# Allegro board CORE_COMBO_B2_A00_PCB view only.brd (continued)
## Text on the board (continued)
User.45: list("[Package] BOTTOM" "275.Pkg to Place Keepout Spacing" "0 MIL [NONE]" "138.58 MIL" "-138.58 MIL" "DRC ERROR CLASS/PACKAGE_BOTTOM" "[Shape] Package Keepout/Bottom ((-3125.93 3041.94) (-2426.72 3992.42))" "[Shape] Package Geometry/Place_Bound_Bottom ((-3045.92 3121.96) (-2506.71 3912.44))" list(-3026.600000 3824.480000) nil)@@@list("kelly1_pan" "2016/03/17 14:53:36" nil "P143000035-PC" "10i-core_combo_b2.20")@@@list("jennifer_hsu" "2016/03/21 14:55:31" nil "p143000039-pc" "10i-core_combo_b2.20") | list("[Package] BOTTOM" "276.Pkg to Place Keepin Spacing" "0 MIL [NONE]" "0 MIL" "0.00 MIL" "DRC ERROR CLASS/PACKAGE_BOTTOM" "[Shape] Package Keepin/All ((-2957.43 -894.53) (7886.82 5054.84))" "[Shape] Package Geometry/Place_Bound_Bottom ((-3045.92 3121.96) (-2506.71 3912.44))" list(-2927.260000 3167.040000) nil)@@@list("kelly1_pan" "2016/03/17 14:53:36" nil "P143000035-PC" "10i-core_combo_b2.20")@@@list("jennifer_hsu" "2016/03/21 14:55:32" nil "p143000039-pc" "10i-core_combo_b2.20") | list("[Package] BOTTOM" "274.Pkg to Place Keepout Spacing" "0 MIL [NONE]" "138.58 MIL" "-138.58 MIL" "DRC ERROR CLASS/PACKAGE_BOTTOM" "[Shape] Package Keepout/Bottom ((-3125.93 2331.37) (-2370.0 3171.49))" "[Shape] Package Geometry/Place_Bound_Bottom ((-3045.92 3121.96) (-2506.71 3912.44))" list(-2927.260000 3125.380000) nil)@@@list("kelly1_pan" "2016/03/17 14:53:35" nil "P143000035-PC" "10i-core_combo_b2.20")@@@list("jennifer_hsu" "2016/03/21 14:55:30" nil "p143000039-pc" "10i-core_combo_b2.20") | list("[Package] BOTTOM" "213.Pkg to Place Keepin Spacing" "0 MIL [NONE]" "955.34 MIL" "-955.34 MIL" "DRC ERROR CLASS/PACKAGE_BOTTOM" "[Shape] Package Keepin/All ((-2957.43 -894.53) (7886.82 5054.84))" "[Shape] Package Geometry/Place_Bound_Bottom ((-3386.36 5554.88) (-3226.36 5714.88))" list(-2913.710000 4676.880000) nil)@@@list("kelly1_pan" "2016/03/17 14:53:52" nil "P143000035-PC" "10i-core_combo_b2.20")@@@list("jennifer_hsu" "2016/03/21 14:54:25" nil "p143000039-pc" "10i-core_combo_b2.20") | list("[Package] TOP" "154.Pkg to Place Keepin Spacing" "0 MIL [NONE]" "955.34 MIL" "-955.34 MIL" "DRC ERROR CLASS/PACKAGE_TOP" "[Shape] Package Keepin/All ((-2957.43 -894.53) (7886.82 5054.84))" "[Shape] Package Geometry/Place_Bound_Top ((-3386.36 5554.88) (-3226.36 5714.88))" list(-2913.710000 4676.880000) nil)@@@list("kelly1_pan" "2016/03/17 14:57:43" nil "P143000035-PC" "10i-core_combo_b2.20")@@@list("jennifer_hsu" "2016/03/21 14:52:20" nil "p143000039-pc" "10i-core_combo_b2.20") | list("[Package] BOTTOM" "216.Pkg to Place Keepin Spacing" "0 MIL [NONE]" "0 MIL" "0.00 MIL" "DRC ERROR CLASS/PACKAGE_BOTTOM" "[Shape] Package Keepin/All ((-2957.43 -894.53) (7886.82 5054.84))" "[Shape] Package Geometry/Place_Bound_Bottom ((-2929.39 4429.59) (-2642.39 4716.59))" list(-2831.290000 4436.960000) nil)@@@list("kelly1_pan" "2016/03/17 14:57:00" nil "P143000035-PC" "10i-core_combo_b2.20")@@@list("jennifer_hsu" "2016/03/21 14:54:28" nil "p143000039-pc" "10i-core_combo_b2.20") | list("[Package] TOP" "189.Pkg to Place Keepin Spacing" "0 MIL [NONE]" "0 MIL" "0.00 MIL" "DRC ERROR CLASS/PACKAGE_TOP" "[Shape] Package Keepin/All ((-2957.43 -894.53) (7886.82 5054.84))" "[Shape] Package Geometry/Place_Bound_Top ((-2929.39 4429.59) (-2642.39 4716.59))" list(-2831.290000 4436.960000) nil)@@@list("kelly1_pan" "2016/03/17 14:59:18" nil "P143000035-PC" "10i-core_combo_b2.20")@@@list("jennifer_hsu" "2016/03/21 14:54:01" nil "p143000039-pc" "10i-core_combo_b2.20") | list("[Package] BOTTOM" "259.Pkg to Place Keepout Spacing" "0 MIL [NONE]" "122.44 MIL" "-122.44 MIL" "DRC ERROR CLASS/PACKAGE_BOTTOM" "[Shape] Package Keepout/Bottom ((-3125.93 3041.94) (-2426.72 3992.42))" "[Shape] Package Geometry/Place_Bound_Bottom ((-3045.93 2411.38) (-2421.17 3091.5))" list(-2733.360000 3041.940000) nil)@@@list("kelly1_pan" "2016/03/17 14:57:22" nil "P143000035-PC" "10i-core_combo_b2.20")@@@list("jennifer_hsu" "2016/03/21 14:55:14" nil "p143000039-pc" "10i-core_combo_b2.20") | list("[Package] BOTTOM" "226.Pkg to Place Keepin Spacing" "0 MIL [NONE]" "44.66 MIL" "-44.66 MIL" "DRC ERROR CLASS/PACKAGE_BOTTOM" "[Shape] Package Keepin/All ((-2957.43 -894.53) (7886.82 5054.84))" "[Shape] Package Geometry/Place_Bound_Bottom ((-2705.5 3802.3) (-2665.5 3842.3))" list(-2688.180000 3886.900000) nil)@@@list("kelly1_pan" "2016/03/17 14:57:08" nil "P143000035-PC" "10i-core_combo_b2.20")@@@list("jennifer_hsu" "2016/03/21 14:54:38" nil "p143000039-pc" "10i-core_combo_b2.20") | list("[Package] TOP" "162.Pkg to Place Keepin Spacing" "0 MIL [NONE]" "44.66 MIL" "-44.66 MIL" "DRC ERROR CLASS/PACKAGE_TOP" "[Shape] Package Keepin/All ((-2957.43 -894.53) (7886.82 5054.84))" "[Shape] Package Geometry/Place_Bound_Top ((-2705.5 3802.3) (-2665.5 3842.3))" list(-2688.180000 3886.900000) nil)@@@list("kelly1_pan" "2016/03/17 14:57:28" nil "P143000035-PC" "10i-core_combo_b2.20")@@@list("jennifer_hsu" "2016/03/21 14:52:33" nil "p143000039-pc" "10i-core_combo_b2.20") | list("[Electrical] ALL" "120.Diffpair Max Uncoupled Length" "200 MIL [DIFFP_UNCOUPLED_LENGTH]" "294.69 MIL" "-94.69 MIL" "DRC ERROR CLASS/ALL" "[PinPair] <uTiL>cId3288<uTiL>.G53:<uTiL>cId4175<uTiL>.7 ((1239.78 2945.81) (-2647.3 3458.14))" "[PinPair] <uTiL>cId3288<uTiL>.F53:<uTiL>cId4175<uTiL>.9 ((1239.78 2971.41) (-2647.3 3497.51))" list(-2647.300000 3497.510000) nil)@@@list("kelly1_pan" "2016/03/17 14:52:43" nil "P143000035-PC" "10i-core_combo_b2.20")@@@list("jennifer_hsu" "2016/03/21 14:51:00" nil "p143000039-pc" "10i-core_combo_b2.20") | list("[Electrical] ALL" "116.Diffpair Max Uncoupled Length" "200 MIL [DIFFP_UNCOUPLED_LENGTH]" "316.78 MIL" "-116.78 MIL" "DRC ERROR CLASS/ALL" "[PinPair] <uTiL>cId3288<uTiL>.F55:<uTiL>cId4175<uTiL>.1 ((1203.78 2971.41) (-2647.3 3340.03))" "[PinPair] <uTiL>cId3288<uTiL>.E55:<uTiL>cId4175<uTiL>.3 ((1203.78 2997.01) (-2647.3 3379.4))" list(-2647.300000 3379.400000) nil)@@@list("kelly1_pan" "2016/03/17 14:52:38" nil "P143000035-PC" "10i-core_combo_b2.20")@@@list("jennifer_hsu" "2016/03/21 14:50:56" nil "p143000039-pc" "10i-core_combo_b2.20") | list("[Package] BOTTOM" "227.Pkg to Place Keepin Spacing" "0 MIL [NONE]" "44.68 MIL" "-44.68 MIL" "DRC ERROR CLASS/PACKAGE_BOTTOM" "[Shape] Package Keepin/All ((-2957.43 -894.53) (7886.82 5054.84))" "[Shape] Package Geometry/Place_Bound_Bottom ((-2705.5 3192.06) (-2665.5 3232.06))" list(-2625.080000 3235.140000) nil)@@@list("kelly1_pan" "2016/03/17 14:53:51" nil "P143000035-PC" "10i-core_combo_b2.20")@@@list("jennifer_hsu" "2016/03/21 14:54:39" nil "p143000039-pc" "10i-core_combo_b2.20") | list("[Package] TOP" "163.Pkg to Place Keepin Spacing" "0 MIL [NONE]" "44.68 MIL" "-44.68 MIL" "DRC ERROR CLASS/PACKAGE_TOP" "[Shape] Package Keepin/All ((-2957.43 -894.53) (7886.82 5054.84))" "[Shape] Package Geometry/Place_Bound_Top ((-2705.5 3192.06) (-2665.5 3232.06))" list(-2625.080000 3235.140000) nil)@@@list("kelly1_pan" "2016/03/17 14:59:17" nil "P143000035-PC" "10i-core_combo_b2.20")@@@list("jennifer_hsu" "2016/03/21 14:53:36" nil "p143000039-pc" "10i-core_combo_b2.20") | list("[Electrical] ALL" "122.Diffpair Max Uncoupled Length" "200 MIL [DIFFP_UNCOUPLED_LENGTH]" "290.05 MIL" "-90.05 MIL" "DRC ERROR CLASS/ALL" "[PinPair] <uTiL>cId3288<uTiL>.G56:<uTiL>cId4175<uTiL>.10 ((1167.78 2945.81) (-2586.28 3517.2))" "[PinPair] <uTiL>cId3288<uTiL>.F56:<uTiL>cId4175<uTiL>.12 ((1167.78 2971.41) (-2586.28 3556.57))" list(-2586.280000 3556.570000) nil)@@@list("kelly1_pan" "2016/03/17 14:52:45" nil "P143000035-PC" "10i-core_combo_b2.20")@@@list("jennifer_hsu" "2016/03/21 14:51:02" nil "p143000039-pc" "10i-core_combo_b2.20") | list("[Electrical] ALL" "118.Diffpair Max Uncoupled Length" "200 MIL [DIFFP_UNCOUPLED_LENGTH]" "290.3 MIL" "-90.30 MIL" "DRC ERROR CLASS/ALL" "[PinPair] <uTiL>cId3288<uTiL>.F58:<uTiL>cId4175<uTiL>.4 ((1131.78 2971.41) (-2586.28 3399.09))" "[PinPair] <uTiL>cId3288<uTiL>.E58:<uTiL>cId4175<uTiL>.6 ((1131.78 2997.01) (-2586.28 3438.46))" list(-2586.280000 3438.460000) nil)@@@list("kelly1_pan" "2016/03/17 14:52:41" nil "P143000035-PC" "10i-core_combo_b2.20")@@@list("jennifer_hsu" "2016/03/21 14:50:58" nil "p143000039-pc" "10i-core_combo_b2.20") | list("[Package] BOTTOM" "225.Pkg to Place Keepin Spacing" "0 MIL [NONE]" "44.66 MIL" "-44.66 MIL" "DRC ERROR CLASS/PACKAGE_BOTTOM" "[Shape] Package Keepin/All ((-2957.43 -894.53) (7886.82 5054.84))" "[Shape] Package Geometry/Place_Bound_Bottom ((-2583.45 2997.18) (-2543.45 3037.18))" list(-2549.080000 3080.230000) nil)@@@list("kelly1_pan" "2016/03/17 14:53:50" nil "P143000035-PC" "10i-core_combo_b2.20")@@@list("jennifer_hsu" "2016/03/21 14:54:37" nil "p143000039-pc" "10i-core_combo_b2.20") | list("[Package] TOP" "186.Pkg to Place Keepin Spacing" "0 MIL [NONE]" "44.66 MIL" "-44.66 MIL" "DRC ERROR CLASS/PACKAGE_TOP" "[Shape] Package Keepin/All ((-2957.43 -894.53) (7886.82 5054.84))" "[Shape] Package Geometry/Place_Bound_Top ((-2583.45 2997.18) (-2543.45 3037.18))" list(-2549.080000 3080.230000) nil)@@@list("kelly1_pan" "2016/03/17 14:57:42" nil "P143000035-PC" "10i-core_combo_b2.20")@@@list("jennifer_hsu" "2016/03/21 14:53:58" nil "p143000039-pc" "10i-core_combo_b2.20") | list("[Electrical] ALL" "129.Diffpair Max Uncoupled Length" "200 MIL [DIFFP_UNCOUPLED_LENGTH]" "310.32 MIL" "-110.32 MIL" "DRC ERROR CLASS/ALL" "[PinPair] <uTiL>cId4161<uTiL>.8:<uTiL>cId3288<uTiL>.C15 ((-2514.24 2830.18) (2090.69 3053.01))" "[PinPair] <uTiL>cId4161<uTiL>.9:<uTiL>cId3288<uTiL>.D15 ((-2514.24 2908.92) (2090.69 3027.41))" list(-2514.240000 2908.920000) nil)@@@list("kelly1_pan" "2016/03/17 14:52:53" nil "P143000035-PC" "10i-core_combo_b2.20")@@@list("jennifer_hsu" "2016/03/21 14:51:13" nil "p143000039-pc" "10i-core_combo_b2.20") | list("[Electrical] ALL" "127.Diffpair Max Uncoupled Length" "200 MIL [DIFFP_UNCOUPLED_LENGTH]" "285.42 MIL" "-85.42 MIL" "DRC ERROR CLASS/ALL" "[PinPair] <uTiL>cId4161<uTiL>.5:<uTiL>cId3288<uTiL>.E10 ((-2514.24 2593.96) (2211.78 2997.01))" "[PinPair] <uTiL>cId4161<uTiL>.6:<uTiL>cId3288<uTiL>.F10 ((-2514.24 2672.7) (2211.78 2971.41))" list(-2514.240000 2672.700000) nil)@@@list("kelly1_pan" "2016/03/17 14:52:51" nil "P143000035-PC" "10i-core_combo_b2.20")@@@list("jennifer_hsu" "2016/03/21 14:51:10" nil "p143000039-pc" "10i-core_combo_b2.20") | list("[Package] BOTTOM" "260.Pkg to Place Keepin Spacing" "0 MIL [NONE]" "0 MIL" "0.00 MIL" "DRC ERROR CLASS/PACKAGE_BOTTOM" "[Shape] Package Keepin/All ((-2957.43 -894.53) (7886.82 5054.84))" "[Shape] Package Geometry/Place_Bound_Bottom ((-3045.93 2411.38) (-2421.17 3091.5))" list(-2502.520000 2463.960000) nil)@@@list("kelly1_pan" "2016/03/17 14:57:22" nil "P143000035-PC" "10i-core_combo_b2.20")@@@list("jennifer_hsu" "2016/03/21 14:55:15" nil "p143000039-pc" "10i-core_combo_b2.20") | list("[Package] BOTTOM" "238.Pkg to Place Keepin Spacing" "0 MIL [NONE]" "44.68 MIL" "-44.68 MIL" "DRC ERROR CLASS/PACKAGE_BOTTOM" "[Shape] Package Keepin/All ((-2957.43 -894.53) (7886.82 5054.84))" "[Shape] Package Geometry/Place_Bound_Bottom ((-2583.45 2465.68) (-2543.45 2505.68))" list(-2498.770000 2485.680000) nil)@@@list("kelly1_pan" "2016/03/17 14:53:41" nil "P143000035-PC" "10i-core_combo_b2.20")@@@list("jennifer_hsu" "2016/03/21 14:54:49" nil "p143000039-pc" "10i-core_combo_b2.20") | list("[Package] TOP" "159.Pkg to Place Keepin Spacing" "0 MIL [NONE]" "44.68 MIL" "-44.68 MIL" "DRC ERROR CLASS/PACKAGE_TOP" "[Shape] Package Keepin/All ((-2957.43 -894.53) (7886.82 5054.84))" "[Shape] Package Geometry/Place_Bound_Top ((-2583.45 2465.68) (-2543.45 2505.68))" list(-2498.770000 2485.680000) nil)@@@list("kelly1_pan" "2016/03/17 14:57:27" nil "P143000035-PC" "10i-core_combo_b2.20")@@@list("jennifer_hsu" "2016/03/21 14:52:29" nil "p143000039-pc" "10i-core_combo_b2.20") | list("[Package] BOTTOM" "248.Pkg to Place Keepin Spacing" "0 MIL [NONE]" "44.67 MIL" "-44.67 MIL" "DRC ERROR CLASS/PACKAGE_BOTTOM" "[Shape] Package Keepin/All ((-2957.43 -894.53) (7886.82 5054.84))" "[Shape] Package Geometry/Place_Bound_Bottom ((-2487.78 4371.98) (-2447.78 4411.98))" list(-2441.380000 4451.010000) nil)@@@list("kelly1_pan" "2016/03/17 14:57:19" nil "P143000035-PC" "10i-core_combo_b2.20")@@@list("jennifer_hsu" "2016/03/21 14:54:59" nil "p143000039-pc" "10i-core_combo_b2.20") | list("[Package] TOP" "195.Pkg to Place Keepin Spacing" "0 MIL [NONE]" "44.67 MIL" "-44.67 MIL" "DRC ERROR CLASS/PACKAGE_TOP" "[Shape] Package Keepin/All ((-2957.43 -894.53) (7886.82 5054.84))" "[Shape] Package Geometry/Place_Bound_Top ((-2487.78 4371.98) (-2447.78 4411.98))" list(-2441.380000 4451.010000) nil)@@@list("kelly1_pan" "2016/03/17 14:59:17" nil "P143000035-PC" "10i-core_combo_b2.20")@@@list("jennifer_hsu" "2016/03/21 14:54:07" nil "p143000039-pc" "10i-core_combo_b2.20") | list("[Package] BOTTOM" "249.Pkg to Place Keepin Spacing" "0 MIL [NONE]" "44.67 MIL" "-44.67 MIL" "DRC ERROR CLASS/PACKAGE_BOTTOM" "[Shape] Package Keepin/All ((-2957.43 -894.53) (7886.82 5054.84))" "[Shape] Package Geometry/Place_Bound_Bottom ((-2487.78 3958.6) (-2447.78 3998.6))" list(-2422.780000 4025.040000) nil)@@@list("kelly1_pan" "2016/03/17 14:53:41" nil "P143000035-PC" "10i-core_combo_b2.20")@@@list("jennifer_hsu" "2016/03/21 14:55:00" nil "p143000039-pc" "10i-core_combo_b2.20") | list("[Package] TOP" "185.Pkg to Place Keepin Spacing" "0 MIL [NONE]" "44.67 MIL" "-44.67 MIL" "DRC ERROR CLASS/PACKAGE_TOP" "[Shape] Package Keepin/All ((-2957.43 -894.53) (7886.82 5054.84))" "[Shape] Package Geometry/Place_Bound_Top ((-2487.78 3958.6) (-2447.78 3998.6))" list(-2422.780000 4025.040000) nil)@@@list("kelly1_pan" "2016/03/17 14:57:47" nil "P143000035-PC" "10i-core_combo_b2.20")@@@list("jennifer_hsu" "2016/03/21 14:53:57" nil "p143000039-pc" "10i-core_combo_b2.20") | list("[Package] BOTTOM" "258.Pkg to Place Keepout Spacing" "0 MIL [NONE]" "122.44 MIL" "-122.44 MIL" "DRC ERROR CLASS/PACKAGE_BOTTOM" "[Shape] Package Keepout/Bottom ((-3125.93 2331.37) (-2370.0 3171.49))" "[Shape] Package Geometry/Place_Bound_Bottom ((-3045.93 2411.38) (-2421.17 3091.5))" list(-2421.170000 2712.070000) nil)@@@list("kelly1_pan" "2016/03/17 14:57:21" nil "P143000035-PC" "10i-core_combo_b2.20")@@@list("jennifer_hsu" "2016/03/21 14:55:11" nil "p143000039-pc" "10i-core_combo_b2.20") | list("[Package] TOP" "156.Pkg to Pkg Spacing" "0 MIL [PACKAGE_HEIGHT_MIN]" "27.56 MIL" "-27.56 MIL" "DRC ERROR CLASS/PACKAGE_TOP" "[Shape] Package Geometry/Place_Bound_Top ((-2379.19 3654.37) (-2252.81 3725.63))" "[Shape] Package Geometry/Place_Bound_Top ((-2377.02 3646.69) (-2254.98 3733.31))" list(-2377.020000 3654.370000) nil)@@@list("kelly1_pan" "2016/03/17 14:59:12" nil "P143000035-PC" "10i-core_combo_b2.20")@@@list("jennifer_hsu" "2016/03/21 14:52:22" nil "p143000039-pc" "10i-core_combo_b2.20") | list("[Package] TOP" "164.Pkg to Pkg Spacing" "0 MIL [PACKAGE_HEIGHT_MIN]" "27.56 MIL" "-27.56 MIL" "DRC ERROR CLASS/PACKAGE_TOP" "[Shape] Package Geometry/Place_Bound_Top ((-2379.19 3554.37) (-2252.81 3625.63))" "[Shape] Package Geometry/Place_Bound_Top ((-2377.02 3546.69) (-2254.98 3633.31))" list(-2377.020000 3554.370000) nil)@@@list("kelly1_pan" "2016/03/17 14:57:45" nil "P143000035-PC" "10i-core_combo_b2.20")@@@list("jennifer_hsu" "2016/03/21 14:53:37" nil "p143000039-pc" "10i-core_combo_b2.20") | list("[Package] TOP" "179.Pkg to Pkg Spacing" "0 MIL [PACKAGE_HEIGHT_MIN]" "27.56 MIL" "-27.56 MIL" "DRC ERROR CLASS/PACKAGE_TOP" "[Shape] Package Geometry/Place_Bound_Top ((-2379.19 3455.37) (-2252.81 3526.63))" "[Shape] Package Geometry/Place_Bound_Top ((-2377.02 3447.69) (-2254.98 3534.31))" list(-2377.020000 3455.370000) nil)@@@list("kelly1_pan" "2016/03/17 15:01:00" nil "P143000035-PC" "10i-core_combo_b2.20")@@@list("jennifer_hsu" "2016/03/21 14:53:51" nil "p143000039-pc" "10i-core_combo_b2.20") | list("[Package] TOP" "191.Pkg to Pkg Spacing" "0 MIL [PACKAGE_HEIGHT_MIN]" "27.56 MIL" "-27.56 MIL" "DRC ERROR CLASS/PACKAGE_TOP" "[Shape] Package Geometry/Place_Bound_Top ((-2379.19 3354.37) (-2252.81 3425.63))" "[Shape] Package Geometry/Place_Bound_Top ((-2377.02 3346.69) (-2254.98 3433.31))" list(-2377.020000 3354.370000) nil)@@@list("kelly1_pan" "2016/03/17 14:59:19" nil "P143000035-PC" "10i-core_combo_b2.20")@@@list("jennifer_hsu" "2016/03/21 14:54:03" nil "p143000039-pc" "10i-core_combo_b2.20") | list("[Package] BOTTOM" "254.Pkg to Place Keepin Spacing" "0 MIL [NONE]" "0 MIL" "0.00 MIL" "DRC ERROR CLASS/PACKAGE_BOTTOM" "[Shape] Package Keepin/All ((-2957.43 -894.53) (7886.82 5054.84))" "[Shape] Package Geometry/Place_Bound_Bottom ((-2338.84 2393.37) (-2051.84 2680.37))" list(-2304.780000 2444.050000) nil)@@@list("kelly1_pan" "2016/03/17 14:53:40" nil "P143000035-PC" "10i-core_combo_b2.20")@@@list("jennifer_hsu" "2016/03/21 14:55:07" nil "p143000039-pc" "10i-core_combo_b2.20") | list("[Package] TOP" "193.Pkg to Place Keepin Spacing" "0 MIL [NONE]" "0 MIL" "0.00 MIL" "DRC ERROR CLASS/PACKAGE_TOP" "[Shape] Package Keepin/All ((-2957.43 -894.53) (7886.82 5054.84))" "[Shape] Package Geometry/Place_Bound_Top ((-2338.84 2393.37) (-2051.84 2680.37))" list(-2304.780000 2444.050000) nil)@@@list("kelly1_pan" "2016/03/17 15:00:52" nil "P143000035-PC" "10i-core_combo_b2.20")@@@list("jennifer_hsu" "2016/03/21 14:54:05" nil "p143000039-pc" "10i-core_combo_b2.20") | list("[Package] BOTTOM" "234.Pkg to Pkg Spacing" "0 MIL [PACKAGE_HEIGHT_MIN]" "27.56 MIL" "-27.56 MIL" "DRC ERROR CLASS/PACKAGE_BOTTOM" "[Shape] Package Geometry/Place_Bound_Bottom ((-2303.69 2808.37) (-2177.31 2879.63))" "[Shape] Package Geometry/Place_Bound_Bottom ((-2301.52 2800.69) (-2179.48 2887.31))" list(-2301.520000 2808.370000) nil)@@@list("kelly1_pan" "2016/03/17 14:57:03" nil "P143000035-PC" "10i-core_combo_b2.20")@@@list("jennifer_hsu" "2016/03/21 14:54:46" nil "p143000039-pc" "10i-core_combo_b2.20") | list("[Package] TOP" "177.Pkg to Place Keepin Spacing" "0 MIL [NONE]" "862.94 MIL" "-862.94 MIL" "DRC ERROR CLASS/PACKAGE_TOP" "[Shape] Package Keepin/All ((-2957.43 -894.53) (7886.82 5054.84))" "[Shape] Package Geometry/Place_Bound_Top ((-2351.42 5539.82) (-2161.3 5729.94))" list(-2256.350000 4676.880000) nil)@@@list("kelly1_pan" "2016/03/17 15:00:56" nil "P143000035-PC" "10i-core_combo_b2.20")@@@list("jennifer_hsu" "2016/03/21 14:53:49" nil "p143000039-pc" "10i-core_combo_b2.20") | list("[Package] BOTTOM" "219.Pkg to Pkg Spacing" "0 MIL [PACKAGE_HEIGHT_MIN]" "27.56 MIL" "-27.56 MIL" "DRC ERROR CLASS/PACKAGE_BOTTOM" "[Shape] Package Geometry/Place_Bound_Bottom ((-2223.31 4307.57) (-2096.93 4378.83))" "[Shape] Package Geometry/Place_Bound_Bottom ((-2221.14 4299.89) (-2099.1 4386.51))" list(-2221.140000 4307.570000) nil)@@@list("kelly1_pan" "2016/03/17 14:53:26" nil "P143000035-PC" "10i-core_combo_b2.20")@@@list("jennifer_hsu" "2016/03/21 14:54:31" nil "p143000039-pc" "10i-core_combo_b2.20") | list("[Package] TOP" "165.Pkg to Pkg Spacing" "0 MIL [PACKAGE_HEIGHT_MIN]" "27.56 MIL" "-27.56 MIL" "DRC ERROR CLASS/PACKAGE_TOP" "[Shape] Package Geometry/Place_Bound_Top ((-2208.19 2814.37) (-2081.81 2885.63))" "[Shape] Package Geometry/Place_Bound_Top ((-2206.02 2806.69) (-2083.98 2893.31))" list(-2206.020000 2814.370000) nil)@@@list("kelly1_pan" "2016/03/17 14:57:31" nil "P143000035-PC" "10i-core_combo_b2.20")@@@list("jennifer_hsu" "2016/03/21 14:53:38" nil "p143000039-pc" "10i-core_combo_b2.20") | list("[Package] TOP" "173.Pkg to Pkg Spacing" "0 MIL [PACKAGE_HEIGHT_MIN]" "27.56 MIL" "-27.56 MIL" "DRC ERROR CLASS/PACKAGE_TOP" "[Shape] Package Geometry/Place_Bound_Top ((-2208.19 2724.37) (-2081.81 2795.63))" "[Shape] Package Geometry/Place_Bound_Top ((-2206.02 2716.69) (-2083.98 2803.31))" list(-2206.020000 2724.370000) nil)@@@list("kelly1_pan" "2016/03/17 14:57:38" nil "P143000035-PC" "10i-core_combo_b2.20")@@@list("jennifer_hsu" "2016/03/21 14:53:45" nil "p143000039-pc" "10i-core_combo_b2.20") | list("[Package] BOTTOM" "271.Pkg to Place Keepin Spacing" "0 MIL [NONE]" "862.94 MIL" "-862.94 MIL" "DRC ERROR CLASS/PACKAGE_BOTTOM" "[Shape] Package Keepin/All ((-2957.43 -894.53) (7886.82 5054.84))" "[Shape] Package Geometry/Place_Bound_Bottom ((-2151.42 5539.82) (-1961.3 5729.94))" list(-2056.370000 4676.880000) nil)@@@list("kelly1_pan" "2016/03/17 14:53:33" nil "P143000035-PC" "10i-core_combo_b2.20")@@@list("jennifer_hsu" "2016/03/21 14:55:27" nil "p143000039-pc" "10i-core_combo_b2.20") | list("[Package] BOTTOM" "246.Pkg to Pkg Spacing" "0 MIL [PACKAGE_HEIGHT_MIN]" "342.52 MIL" "-342.52 MIL" "DRC ERROR CLASS/PACKAGE_BOTTOM" "[Shape] Package Geometry/Place_Bound_Bottom ((-2637.27 4460.93) (-2030.57 4662.05))" "[Shape] Package Geometry/Place_Bound_Bottom ((-2055.44 3647.63) (-1701.85 4533.61))" list(-2055.440000 4511.100000) nil)@@@list("kelly1_pan" "2016/03/17 14:57:03" nil "P143000035-PC" "10i-core_combo_b2.20")@@@list("jennifer_hsu" "2016/03/21 14:54:57" nil "p143000039-pc" "10i-core_combo_b2.20") | list("[Electrical] ALL" "106.Diffpair Max Uncoupled Length" "200 MIL [DIFFP_UNCOUPLED_LENGTH]" "205.57 MIL" "-5.57 MIL" "DRC ERROR CLASS/ALL" "[PinPair] <uTiL>cId6551<uTiL>.5:<uTiL>cId3288<uTiL>.AF8 ((-1998.29 4415.42) (2265.88 2580.01))" "[PinPair] <uTiL>cId6551<uTiL>.3:<uTiL>cId3288<uTiL>.AF9 ((-1998.29 4435.11) (2240.28 2580.01))" list(-1998.290000 4435.110000) nil)@@@list("kelly1_pan" "2016/03/17 14:52:09" nil "P143000035-PC" "10i-core_combo_b2.20")@@@list("jennifer_hsu" "2016/03/21 14:50:45" nil "p143000039-pc" "10i-core_combo_b2.20") | list("[Electrical] ALL" "124.Diffpair Max Uncoupled Length" "200 MIL [DIFFP_UNCOUPLED_LENGTH]" "222.52 MIL" "-22.52 MIL" "DRC ERROR CLASS/ALL" "[PinPair] <uTiL>cId6551<uTiL>.35:<uTiL>cId3288<uTiL>.D19 ((-1998.29 4120.15) (1993.13 3027.41))" "[PinPair] <uTiL>cId6551<uTiL>.37:<uTiL>cId3288<uTiL>.C19 ((-1998.29 4100.46) (1993.13 3053.01))" list(-1998.290000 4100.460000) nil)@@@list("kelly1_pan" "2016/03/17 14:52:48" nil "P143000035-PC" "10i-core_combo_b2.20")@@@list("jennifer_hsu" "2016/03/21 14:51:05" nil "p143000039-pc" "10i-core_combo_b2.20") | list("[Package] BOTTOM" "220.Pkg to Pkg Spacing" "0 MIL [PACKAGE_HEIGHT_MIN]" "27.56 MIL" "-27.56 MIL" "DRC ERROR CLASS/PACKAGE_BOTTOM" "[Shape] Package Geometry/Place_Bound_Bottom ((-1950.63 2991.81) (-1879.37 3118.19))" "[Shape] Package Geometry/Place_Bound_Bottom ((-1958.31 2993.98) (-1871.69 3116.02))" list(-1950.630000 2993.980000) nil)@@@list("kelly1_pan" "2016/03/17 14:53:45" nil "P143000035-PC" "10i-core_combo_b2.20")@@@list("jennifer_hsu" "2016/03/21 14:54:32" nil "p143000039-pc" "10i-core_combo_b2.20") | list("[Electrical] ALL" "132.Diffpair Max Uncoupled Length" "200 MIL [DIFFP_UNCOUPLED_LENGTH]" "201.28 MIL" "-1.28 MIL" "DRC ERROR CLASS/ALL" "[PinPair] <uTiL>cId4179<uTiL>.18:<uTiL>cId3288<uTiL>.C45 ((-1072.1 3063.42) (1407.77 3053.01))" "[PinPair] <uTiL>cId4179<uTiL>.17:<uTiL>cId3288<uTiL>.D46 ((-1052.42 3063.42) (1385.59 3040.21))" list(-1052.420000 3063.420000) nil)@@@list("kelly1_pan" "2016/03/17 14:53:13" nil "P143000035-PC" "10i-core_combo_b2.20")@@@list("jennifer_hsu" "2016/03/21 14:51:19" nil "p143000039-pc" "10i-core_combo_b2.20") | list("[Package] BOTTOM" "250.Pkg to Place Keepin Spacing" "0 MIL [NONE]" "489.82 MIL" "-489.82 MIL" "DRC ERROR CLASS/PACKAGE_BOTTOM" "[Shape] Package Keepin/All ((-2957.43 -894.53) (7886.82 5054.84))" "[Shape] Package Geometry/Place_Bound_Bottom ((-695.32 5539.82) (-505.2 5729.94))" list(-525.140000 5054.840000) nil)@@@list("kelly1_pan" "2016/03/17 14:53:43" nil "P143000035-PC" "10i-core_combo_b2.20")@@@list("jennifer_hsu" "2016/03/21 14:55:01" nil "p143000039-pc" "10i-core_combo_b2.20") | list("[Package] BOTTOM" "272.Pkg to Place Keepin Spacing" "0 MIL [NONE]" "0 MIL" "0.00 MIL" "DRC ERROR CLASS/PACKAGE_BOTTOM" "[Shape] Package Keepin/All ((-2957.43 -894.53) (7886.82 5054.84))" "[Shape] Package Geometry/Place_Bound_Bottom ((-619.15 4838.23) (-332.15 5125.23))" list(-525.140000 4847.030000) nil)@@@list("kelly1_pan" "2016/03/17 14:53:34" nil "P143000035-PC" "10i-core_combo_b2.20")@@@list("jennifer_hsu" "2016/03/21 14:55:28" nil "p143000039-pc" "10i-core_combo_b2.20") | list("[Package] TOP" "178.Pkg to Place Keepin Spacing" "0 MIL [NONE]" "0 MIL" "0.00 MIL" "DRC ERROR CLASS/PACKAGE_TOP" "[Shape] Package Keepin/All ((-2957.43 -894.53) (7886.82 5054.84))" "[Shape] Package Geometry/Place_Bound_Top ((-619.15 4838.23) (-332.15 5125.23))" list(-525.140000 4847.030000) nil)@@@list("kelly1_pan" "2016/03/17 15:00:48" nil "P143000035-PC" "10i-core_combo_b2.20")@@@list("jennifer_hsu" "2016/03/21 14:53:50" nil "p143000039-pc" "10i-core_combo_b2.20") | list("[Package] BOTTOM" "255.Pkg to Pkg Spacing" "0 MIL [PACKAGE_HEIGHT_MIN]" "0 MIL" "0.00 MIL" "DRC ERROR CLASS/PACKAGE_BOTTOM" "[Shape] Package Geometry/Place_Bound_Bottom ((-619.15 4838.23) (-332.15 5125.23))" "[Shape] Package Geometry/Place_Bound_Bottom ((-505.16 4753.49) (-446.16 4861.49))" list(-503.750000 4841.010000) nil)@@@list("kelly1_pan" "2016/03/17 14:53:31" nil "P143000035-PC" "10i-core_combo_b2.20")@@@list("jennifer_hsu" "2016/03/21 14:55:09" nil "p143000039-pc" "10i-core_combo_b2.20") | list("[Package] TOP" "169.Pkg to Pkg Spacing" "0 MIL [PACKAGE_HEIGHT_MIN]" "0 MIL" "0.00 MIL" "DRC ERROR CLASS/PACKAGE_TOP" "[Shape] Package Geometry/Place_Bound_Top ((-619.15 4838.23) (-332.15 5125.23))" "[Shape] Package Geometry/Place_Bound_Top ((-505.16 4753.49) (-446.16 4861.49))" list(-503.750000 4841.010000) nil)@@@list("kelly1_pan" "2016/03/17 14:59:14" nil "P143000035-PC" "10i-core_combo_b2.20")@@@list("jennifer_hsu" "2016/03/21 14:53:41" nil "p143000039-pc" "10i-core_combo_b2.20") | list("[Package] TOP" "180.Pkg to Pkg Spacing" "0 MIL [PACKAGE_HEIGHT_MIN]" "118.11 MIL" "-118.11 MIL" "DRC ERROR CLASS/PACKAGE_TOP" "[Shape] Package Geometry/Place_Bound_Top ((-377.4 2787.6) (-352.4 2812.6))" "[Shape] Package Geometry/Place_Bound_Top ((-472.5 2658.17) (-117.3 2942.03))" list(-377.400000 2800.100000) nil)@@@list("kelly1_pan" "2016/03/17 15:00:45" nil "P143000035-PC" "10i-core_combo_b2.20")@@@list("jennifer_hsu" "2016/03/21 14:53:52" nil "p143000039-pc" "10i-core_combo_b2.20") | list("[Package] BOTTOM" "206.Pkg to Place Keepin Spacing" "0 MIL [NONE]" "2533.33 MIL" "-2533.33 MIL" "DRC ERROR CLASS/PACKAGE_BOTTOM" "[Shape] Package Keepin/All ((-2957.43 -894.53) (7886.82 5054.84))" "[Shape] Package Geometry/Place_Bound_Bottom ((-2851.42 -1307.03) (-2661.3 -1116.91))" list(-369.630000 -111.070000) nil)@@@list("kelly1_pan" "2016/03/17 14:57:08" nil "P143000035-PC" "10i-core_combo_b2.20")@@@list("jennifer_hsu" "2016/03/21 14:54:18" nil "p143000039-pc" "10i-core_combo_b2.20") | list("[Package] BOTTOM" "228.Pkg to Place Keepin Spacing" "0 MIL [NONE]" "3056.3 MIL" "-3056.30 MIL" "DRC ERROR CLASS/PACKAGE_BOTTOM" "[Shape] Package Keepin/All ((-2957.43 -894.53) (7886.82 5054.84))" "[Shape] Package Geometry/Place_Bound_Bottom ((-3386.36 -1291.97) (-3226.36 -1131.97))" list(-369.630000 -111.070000) nil)@@@list("kelly1_pan" "2016/03/17 14:53:53" nil "P143000035-PC" "10i-core_combo_b2.20")@@@list("jennifer_hsu" "2016/03/21 14:54:40" nil "p143000039-pc" "10i-core_combo_b2.20") | list("[Package] TOP" "155.Pkg to Place Keepin Spacing" "0 MIL [NONE]" "2716.19 MIL" "-2716.19 MIL" "DRC ERROR CLASS/PACKAGE_TOP" "[Shape] Package Keepin/All ((-2957.43 -894.53) (7886.82 5054.84))" "[Shape] Package Geometry/Place_Bound_Top ((-3051.42 -1307.03) (-2861.3 -1116.91))" list(-369.630000 -111.070000) nil)@@@list("kelly1_pan" "2016/03/17 15:00:56" nil "P143000035-PC" "10i-core_combo_b2.20")@@@list("jennifer_hsu" "2016/03/21 14:52:21" nil "p143000039-pc" "10i-core_combo_b2.20") | list("[Package] TOP" "187.Pkg to Place Keepin Spacing" "0 MIL [NONE]" "3056.3 MIL" "-3056.30 MIL" "DRC ERROR CLASS/PACKAGE_TOP" "[Shape] Package Keepin/All ((-2957.43 -894.53) (7886.82 5054.84))" "[Shape] Package Geometry/Place_Bound_Top ((-3386.36 -1291.97) (-3226.36 -1131.97))" list(-369.630000 -111.070000) nil)@@@list("kelly1_pan" "2016/03/17 14:57:28" nil "P143000035-PC" "10i-core_combo_b2.20")@@@list("jennifer_hsu" "2016/03/21 14:53:59" nil "p143000039-pc" "10i-core_combo_b2.20") | list("[Package] TOP" "197.Pkg to Place Keepin Spacing" "0 MIL [NONE]" "1029.74 MIL" "-1029.74 MIL" "DRC ERROR CLASS/PACKAGE_TOP" "[Shape] Package Keepin/All ((-2957.43 -894.53) (7886.82 5054.84))" "[Shape] Package Geometry/Place_Bound_Top ((-695.32 -1307.03) (-505.2 -1116.91))" list(-369.630000 -111.070000) nil)@@@list("kelly1_pan" "2016/03/17 14:57:34" nil "P143000035-PC" "10i-core_combo_b2.20")@@@list("jennifer_hsu" "2016/03/21 14:54:09" nil "p143000039-pc" "10i-core_combo_b2.20") | list("[Package] BOTTOM" "266.Pkg to Place Keepin Spacing" "0 MIL [NONE]" "34.4 MIL" "-34.40 MIL" "DRC ERROR CLASS/PACKAGE_BOTTOM" "[Shape] Package Keepin/All ((-2957.43 -894.53) (7886.82 5054.84))" "[Shape] Package Geometry/Place_Bound_Bottom ((-369.37 5089.24) (-310.31 5187.67))" list(-369.370000 5054.840000) nil)@@@list("kelly1_pan" "2016/03/17 14:57:05" nil "P143000035-PC" "10i-core_combo_b2.20")@@@list("jennifer_hsu" "2016/03/21 14:55:22" nil "p143000039-pc" "10i-core_combo_b2.20") | list("[Package] BOTTOM" "253.Pkg to Place Keepin Spacing" "0 MIL [NONE]" "0 MIL" "0.00 MIL" "DRC ERROR CLASS/PACKAGE_BOTTOM" "[Shape] Package Keepin/All ((-2957.43 -894.53) (7886.82 5054.84))" "[Shape] Package Geometry/Place_Bound_Bottom ((-408.53 -146.0) (-121.53 141.0))" list(-358.860000 -111.070000) nil)@@@list("kelly1_pan" "2016/03/17 14:56:59" nil "P143000035-PC" "10i-core_combo_b2.20")@@@list("jennifer_hsu" "2016/03/21 14:55:06" nil "p143000039-pc" "10i-core_combo_b2.20") | list("[Package] TOP" "146.Pkg to Place Keepin Spacing" "0 MIL [NONE]" "0 MIL" "0.00 MIL" "DRC ERROR CLASS/PACKAGE_TOP" "[Shape] Package Keepin/All ((-2957.43 -894.53) (7886.82 5054.84))" "[Shape] Package Geometry/Place_Bound_Top ((-408.53 -146.0) (-121.53 141.0))" list(-358.860000 -111.070000) nil)@@@list("kelly1_pan" "2016/03/17 14:57:30" nil "P143000035-PC" "10i-core_combo_b2.20")@@@list("jennifer_hsu" "2016/03/21 14:52:12" nil "p143000039-pc" "10i-core_combo_b2.20") | list("[Package] BOTTOM" "204.Pkg to Place Keepin Spacing" "0 MIL [NONE]" "44.67 MIL" "-44.67 MIL" "DRC ERROR CLASS/PACKAGE_BOTTOM" "[Shape] Package Keepin/All ((-2957.43 -894.53) (7886.82 5054.84))" "[Shape] Package Geometry/Place_Bound_Bottom ((-314.55 4927.5) (-274.55 4967.5))" list(-339.550000 4993.950000) nil)@@@list("kelly1_pan" "2016/03/17 14:53:21" nil "P143000035-PC" "10i-core_combo_b2.20")@@@list("jennifer_hsu" "2016/03/21 14:54:16" nil "p143000039-pc" "10i-core_combo_b2.20") | list("[Package] TOP" "182.Pkg to Place Keepin Spacing" "0 MIL [NONE]" "44.67 MIL" "-44.67 MIL" "DRC ERROR CLASS/PACKAGE_TOP" "[Shape] Package Keepin/All ((-2957.43 -894.53) (7886.82 5054.84))" "[Shape] Package Geometry/Place_Bound_Top ((-314.55 4927.5) (-274.55 4967.5))" list(-339.550000 4993.950000) nil)@@@list("kelly1_pan" "2016/03/17 15:00:53" nil "P143000035-PC" "10i-core_combo_b2.20")@@@list("jennifer_hsu" "2016/03/21 14:53:54" nil "p143000039-pc" "10i-core_combo_b2.20") | list("[Package] BOTTOM" "211.Pkg to Place Keepin Spacing" "0 MIL [NONE]" "0 MIL" "0.00 MIL" "DRC ERROR CLASS/PACKAGE_BOTTOM" "[Shape] Package Keepin/All ((-2957.43 -894.53) (7886.82 5054.84))" "[Shape] Package Geometry/Place_Bound_Bottom ((-309.75 4792.76) (948.97 5374.48))" list(-231.740000 4902.470000) nil)@@@list("kelly1_pan" "2016/03/17 14:53:39" nil "P143000035-PC" "10i-core_combo_b2.20")@@@list("jennifer_hsu" "2016/03/21 14:54:23" nil "p143000039-pc" "10i-core_combo_b2.20") | list("[Package] TOP" "181.Pkg to Pkg Spacing" "0 MIL [PACKAGE_HEIGHT_MIN]" "118.11 MIL" "-118.11 MIL" "DRC ERROR CLASS/PACKAGE_TOP" "[Shape] Package Geometry/Place_Bound_Top ((-237.4 2787.6) (-212.4 2812.6))" "[Shape] Package Geometry/Place_Bound_Top ((-472.5 2658.17) (-117.3 2942.03))" list(-212.400000 2800.100000) nil)@@@list("kelly1_pan" "2016/03/17 15:00:46" nil "P143000035-PC" "10i-core_combo_b2.20")@@@list("jennifer_hsu" "2016/03/21 14:53:53" nil "p143000039-pc" "10i-core_combo_b2.20") | list("[Package] BOTTOM" "237.Pkg to Place Keepin Spacing" "0 MIL [NONE]" "0 MIL" "0.00 MIL" "DRC ERROR CLASS/PACKAGE_BOTTOM" "[Shape] Package Keepin/All ((-2957.43 -894.53) (7886.82 5054.84))" "[Shape] Package Geometry/Place_Bound_Bottom ((-211.88 98.29) (16.81 455.31))" list(-136.790000 442.150000) nil)@@@list("kelly1_pan" "2016/03/17 14:53:39" nil "P143000035-PC" "10i-core_combo_b2.20")@@@list("jennifer_hsu" "2016/03/21 14:54:48" nil "p143000039-pc" "10i-core_combo_b2.20") | list("[Package] BOTTOM" "252.Pkg to Pkg Spacing" "0 MIL [PACKAGE_HEIGHT_MIN]" "0 MIL" "0.00 MIL" "DRC ERROR CLASS/PACKAGE_BOTTOM" "[Shape] Package Geometry/Place_Bound_Bottom ((-168.37 -104.83) (-109.37 -45.83))" "[Shape] Package Geometry/Place_Bound_Bottom ((-408.53 -146.0) (-121.53 141.0))" list(-128.800000 -47.600000) nil)@@@list("kelly1_pan" "2016/03/17 14:55:38" nil "P143000035-PC" "10i-core_combo_b2.20")@@@list("jennifer_hsu" "2016/03/21 14:55:04" nil "p143000039-pc" "10i-core_combo_b2.20") | list("[Package] TOP" "145.Pkg to Pkg Spacing" "0 MIL [PACKAGE_HEIGHT_MIN]" "0 MIL" "0.00 MIL" "DRC ERROR CLASS/PACKAGE_TOP" "[Shape] Package Geometry/Place_Bound_Top ((-168.37 -104.83) (-109.37 -45.83))" "[Shape] Package Geometry/Place_Bound_Top ((-408.53 -146.0) (-121.53 141.0))" list(-128.800000 -47.600000) nil)@@@list("kelly1_pan" "2016/03/17 14:57:29" nil "P143000035-PC" "10i-core_combo_b2.20")@@@list("jennifer_hsu" "2016/03/21 14:52:10" nil "p143000039-pc" "10i-core_combo_b2.20") | list("[Package] BOTTOM" "236.Pkg to Pkg Spacing" "0 MIL [PACKAGE_HEIGHT_MIN]" "196.85 MIL" "-196.85 MIL" "DRC ERROR CLASS/PACKAGE_BOTTOM" "[Shape] Package Geometry/Place_Bound_Bottom ((-26.77 5.29) (3048.69 1006.72))" "[Shape] Package Geometry/Place_Bound_Bottom ((-211.88 98.29) (16.81 455.31))" list(-26.770000 455.310000) nil)@@@list("kelly1_pan" "2016/03/17 14:53:38" nil "P143000035-PC" "10i-core_combo_b2.20")@@@list("jennifer_hsu" "2016/03/21 14:54:48" nil "p143000039-pc" "10i-core_combo_b2.20") | list("[Package] BOTTOM" "205.Pkg to Place Keepin Spacing" "0 MIL [NONE]" "44.67 MIL" "-44.67 MIL" "DRC ERROR CLASS/PACKAGE_BOTTOM" "[Shape] Package Keepin/All ((-2957.43 -894.53) (7886.82 5054.84))" "[Shape] Package Geometry/Place_Bound_Bottom ((-31.09 4927.5) (8.91 4967.5))" list(33.910000 4993.940000) nil)@@@list("kelly1_pan" "2016/03/17 14:57:19" nil "P143000035-PC" "10i-core_combo_b2.20")@@@list("jennifer_hsu" "2016/03/21 14:54:17" nil "p143000039-pc" "10i-core_combo_b2.20") | list("[Package] TOP" "183.Pkg to Place Keepin Spacing" "0 MIL [NONE]" "44.67 MIL" "-44.67 MIL" "DRC ERROR CLASS/PACKAGE_TOP" "[Shape] Package Keepin/All ((-2957.43 -894.53) (7886.82 5054.84))" "[Shape] Package Geometry/Place_Bound_Top ((-31.09 4927.5) (8.91 4967.5))" list(33.910000 4993.940000) nil)@@@list("kelly1_pan" "2016/03/17 14:59:15" nil "P143000035-PC" "10i-core_combo_b2.20")@@@list("jennifer_hsu" "2016/03/21 14:53:55" nil "p143000039-pc" "10i-core_combo_b2.20") | list("[Electrical] ALL" "140.Diffpair Max Uncoupled Length" "200 MIL [DIFFP_UNCOUPLED_LENGTH]" "225.91 MIL" "-25.91 MIL" "DRC ERROR CLASS/ALL" "[PinPair] <uTiL>cId3288<uTiL>.AG70:<uTiL>cId4181<uTiL>.13 ((863.36 2560.23) (315.09 374.64))" "[PinPair] <uTiL>cId3288<uTiL>.AG69:<uTiL>cId4181<uTiL>.11 ((888.96 2556.33) (295.41 374.64))" list(295.410000 374.640000) nil)@@@list("kelly1_pan" "2016/03/17 14:53:19" nil "P143000035-PC" "10i-core_combo_b2.20")@@@list("jennifer_hsu" "2016/03/21 14:52:04" nil "p143000039-pc" "10i-core_combo_b2.20") | list("[Package] BOTTOM" "267.Pkg to Place Keepin Spacing" "0 MIL [NONE]" "44.66 MIL" "-44.66 MIL" "DRC ERROR CLASS/PACKAGE_BOTTOM" "[Shape] Package Keepin/All ((-2957.43 -894.53) (7886.82 5054.84))" "[Shape] Package Geometry/Place_Bound_Bottom ((630.32 4927.5) (670.32 4967.5))" list(605.330000 4993.940000) nil)@@@list("kelly1_pan" "2016/03/17 14:53:46" nil "P143000035-PC" "10i-core_combo_b2.20")@@@list("jennifer_hsu" "2016/03/21 14:55:24" nil "p143000039-pc" "10i-core_combo_b2.20") | list("[Package] TOP" "151.Pkg to Place Keepin Spacing" "0 MIL [NONE]" "44.66 MIL" "-44.66 MIL" "DRC ERROR CLASS/PACKAGE_TOP" "[Shape] Package Keepin/All ((-2957.43 -894.53) (7886.82 5054.84))" "[Shape] Package Geometry/Place_Bound_Top ((630.32 4927.5) (670.32 4967.5))" list(605.330000 4993.940000) nil)@@@list("kelly1_pan" "2016/03/17 14:57:32" nil "P143000035-PC" "10i-core_combo_b2.20")@@@list("jennifer_hsu" "2016/03/21 14:52:17" nil "p143000039-pc" "10i-core_combo_b2.20") | list("[Package] BOTTOM" "280.Pkg to Place Keepin Spacing" "0 MIL [NONE]" "34.4 MIL" "-34.40 MIL" "DRC ERROR CLASS/PACKAGE_BOTTOM" "[Shape] Package Keepin/All ((-2957.43 -894.53) (7886.82 5054.84))" "[Shape] Package Geometry/Place_Bound_Bottom ((949.53 5089.24) (1008.59 5187.67))" list(978.790000 5054.840000) nil)@@@list("kelly1_pan" "2016/03/17 14:53:30" nil "P143000035-PC" "10i-core_combo_b2.20")@@@list("jennifer_hsu" "2016/03/21 14:55:37" nil "p143000039-pc" "10i-core_combo_b2.20") | list("[Package] BOTTOM" "256.Pkg to Place Keepin Spacing" "0 MIL [NONE]" "44.68 MIL" "-44.68 MIL" "DRC ERROR CLASS/PACKAGE_BOTTOM" "[Shape] Package Keepin/All ((-2957.43 -894.53) (7886.82 5054.84))" "[Shape] Package Geometry/Place_Bound_Bottom ((913.78 4927.5) (953.78 4967.5))" list(978.790000 4993.950000) nil)@@@list("kelly1_pan" "2016/03/17 14:53:47" nil "P143000035-PC" "10i-core_combo_b2.20")@@@list("jennifer_hsu" "2016/03/21 14:55:10" nil "p143000039-pc" "10i-core_combo_b2.20") | list("[Package] TOP" "141.Pkg to Place Keepin Spacing" "0 MIL [NONE]" "44.68 MIL" "-44.68 MIL" "DRC ERROR CLASS/PACKAGE_TOP" "[Shape] Package Keepin/All ((-2957.43 -894.53) (7886.82 5054.84))" "[Shape] Package Geometry/Place_Bound_Top ((913.78 4927.5) (953.78 4967.5))" list(978.790000 4993.950000) nil)@@@list("kelly1_pan" "2016/03/17 15:00:53" nil "P143000035-PC" "10i-core_combo_b2.20")@@@list("jennifer_hsu" "2016/03/21 14:52:05" nil "p143000039-pc" "10i-core_combo_b2.20") | list("[Package] BOTTOM" "212.Pkg to Place Keepin Spacing" "0 MIL [NONE]" "44.67 MIL" "-44.67 MIL" "DRC ERROR CLASS/PACKAGE_BOTTOM" "[Shape] Package Keepin/All ((-2957.43 -894.53) (7886.82 5054.84))" "[Shape] Package Geometry/Place_Bound_Bottom ((1049.22 4939.07) (1089.22 4979.07))" list(1024.230000 5005.520000) nil)@@@list("kelly1_pan" "2016/03/17 14:57:06" nil "P143000035-PC" "10i-core_combo_b2.20")@@@list("jennifer_hsu" "2016/03/21 14:54:24" nil "p143000039-pc" "10i-core_combo_b2.20") | list("[Package] TOP" "170.Pkg to Place Keepin Spacing" "0 MIL [NONE]" "44.67 MIL" "-44.67 MIL" "DRC ERROR CLASS/PACKAGE_TOP" "[Shape] Package Keepin/All ((-2957.43 -894.53) (7886.82 5054.84))" "[Shape] Package Geometry/Place_Bound_Top ((1049.22 4939.07) (1089.22 4979.07))" list(1024.230000 5005.520000) nil)@@@list("kelly1_pan" "2016/03/17 14:57:25" nil "P143000035-PC" "10i-core_combo_b2.20")@@@list("jennifer_hsu" "2016/03/21 14:53:42" nil "p143000039-pc" "10i-core_combo_b2.20") | list("[Package] BOTTOM" "230.Pkg to Place Keepin Spacing" "0 MIL [NONE]" "0 MIL" "0.00 MIL" "DRC ERROR CLASS/PACKAGE_BOTTOM" "[Shape] Package Keepin/All ((-2957.43 -894.53) (7886.82 5054.84))" "[Shape] Package Geometry/Place_Bound_Bottom ((1066.73 4797.56) (2313.45 5374.63))" list(1066.730000 4894.420000) nil)@@@list("kelly1_pan" "2016/03/17 14:57:16" nil "P143000035-PC" "10i-core_combo_b2.20")@@@list("jennifer_hsu" "2016/03/21 14:54:42" nil "p143000039-pc" "10i-core_combo_b2.20") | list("[Electrical] ALL" "119.Diffpair Max Uncoupled Length" "200 MIL [DIFFP_UNCOUPLED_LENGTH]" "290.43 MIL" "-90.43 MIL" "DRC ERROR CLASS/ALL" "[PinPair] <uTiL>cId3288<uTiL>.E58:<uTiL>cId4175<uTiL>.6 ((1131.78 2997.01) (-2586.28 3438.46))" "[PinPair] <uTiL>cId3288<uTiL>.F58:<uTiL>cId4175<uTiL>.4 ((1131.78 2971.41) (-2586.28 3399.09))" list(1131.780000 2971.410000) nil)@@@list("kelly1_pan" "2016/03/17 14:52:42" nil "P143000035-PC" "10i-core_combo_b2.20")@@@list("jennifer_hsu" "2016/03/21 14:50:59" nil "p143000039-pc" "10i-core_combo_b2.20") | list("[Electrical] ALL" "123.Diffpair Max Uncoupled Length" "200 MIL [DIFFP_UNCOUPLED_LENGTH]" "305.49 MIL" "-105.49 MIL" "DRC ERROR CLASS/ALL" "[PinPair] <uTiL>cId3288<uTiL>.F56:<uTiL>cId4175<uTiL>.12 ((1167.78 2971.41) (-2586.28 3556.57))" "[PinPair] <uTiL>cId3288<uTiL>.G56:<uTiL>cId4175<uTiL>.10 ((1167.78 2945.81) (-2586.28 3517.2))" list(1167.780000 2945.810000) nil)@@@list("kelly1_pan" "2016/03/17 14:52:46" nil "P143000035-PC" "10i-core_combo_b2.20")@@@list("jennifer_hsu" "2016/03/21 14:51:03" nil "p143000039-pc" "10i-core_combo_b2.20") | list("[Electrical] ALL" "117.Diffpair Max Uncoupled Length" "200 MIL [DIFFP_UNCOUPLED_LENGTH]" "295.07 MIL" "-95.07 MIL" "DRC ERROR CLASS/ALL" "[PinPair] <uTiL>cId3288<uTiL>.E55:<uTiL>cId4175<uTiL>.3 ((1203.78 2997.01) (-2647.3 3379.4))" "[PinPair] <uTiL>cId3288<uTiL>.F55:<uTiL>cId4175<uTiL>.1 ((1203.78 2971.41) (-2647.3 3340.03))" list(1203.780000 2971.410000) nil)@@@list("kelly1_pan" "2016/03/17 14:52:39" nil "P143000035-PC" "10i-core_combo_b2.20")@@@list("jennifer_hsu" "2016/03/21 14:50:57" nil "p143000039-pc" "10i-core_combo_b2.20") | list("[Electrical] ALL" "111.Diffpair Max Uncoupled Length" "200 MIL [DIFFP_UNCOUPLED_LENGTH]" "222.09 MIL" "-22.09 MIL" "DRC ERROR CLASS/ALL" "[PinPair] <uTiL>cId6550<uTiL>.47:<uTiL>cId3288<uTiL>.D23 ((1219.42 4299.67) (1895.57 3027.41))" "[PinPair] <uTiL>cId6550<uTiL>.49:<uTiL>cId3288<uTiL>.C23 ((1219.42 4319.36) (1895.57 3053.01))" list(1219.420000 4319.360000) nil)@@@list("kelly1_pan" "2016/03/17 14:52:16" nil "P143000035-PC" "10i-core_combo_b2.20")@@@list("jennifer_hsu" "2016/03/21 14:50:50" nil "p143000039-pc" "10i-core_combo_b2.20") | list("[Electrical] ALL" "121.Diffpair Max Uncoupled Length" "200 MIL [DIFFP_UNCOUPLED_LENGTH]" "303.12 MIL" "-103.12 MIL" "DRC ERROR CLASS/ALL" "[PinPair] <uTiL>cId3288<uTiL>.F53:<uTiL>cId4175<uTiL>.9 ((1239.78 2971.41) (-2647.3 3497.51))" "[PinPair] <uTiL>cId3288<uTiL>.G53:<uTiL>cId4175<uTiL>.7 ((1239.78 2945.81) (-2647.3 3458.14))" list(1239.780000 2945.810000) nil)@@@list("kelly1_pan" "2016/03/17 14:52:44" nil "P143000035-PC" "10i-core_combo_b2.20")@@@list("jennifer_hsu" "2016/03/21 14:51:01" nil "p143000039-pc" "10i-core_combo_b2.20") | list("[Package] BOTTOM" "277.Pkg to Pkg Spacing" "0 MIL [PACKAGE_HEIGHT_MIN]" "27.56 MIL" "-27.56 MIL" "DRC ERROR CLASS/PACKAGE_BOTTOM" "[Shape] Package Geometry/Place_Bound_Bottom ((1286.81 3893.37) (1413.19 3964.63))" "[Shape] Package Geometry/Place_Bound_Bottom ((1288.98 3885.69) (1411.02 3972.31))" list(1288.980000 3893.370000) nil)@@@list("kelly1_pan" "2016/03/17 14:57:11" nil "P143000035-PC" "10i-core_combo_b2.20")@@@list("jennifer_hsu" "2016/03/21 14:55:33" nil "p143000039-pc" "10i-core_combo_b2.20") | list("[Package] BOTTOM" "268.Pkg to Place Keepin Spacing" "0 MIL [NONE]" "44.67 MIL" "-44.67 MIL" "DRC ERROR CLASS/PACKAGE_BOTTOM" "[Shape] Package Keepin/All ((-2957.43 -894.53) (7886.82 5054.84))" "[Shape] Package Geometry/Place_Bound_Bottom ((1332.68 4919.39) (1372.68 4959.39))" list(1397.690000 4985.830000) nil)@@@list("kelly1_pan" "2016/03/17 14:57:05" nil "P143000035-PC" "10i-core_combo_b2.20")@@@list("jennifer_hsu" "2016/03/21 14:55:25" nil "p143000039-pc" "10i-core_combo_b2.20") | list("[Package] TOP" "152.Pkg to Place Keepin Spacing" "0 MIL [NONE]" "44.67 MIL" "-44.67 MIL" "DRC ERROR CLASS/PACKAGE_TOP" "[Shape] Package Keepin/All ((-2957.43 -894.53) (7886.82 5054.84))" "[Shape] Package Geometry/Place_Bound_Top ((1332.68 4919.39) (1372.68 4959.39))" list(1397.690000 4985.830000) nil)@@@list("kelly1_pan" "2016/03/17 14:57:24" nil "P143000035-PC" "10i-core_combo_b2.20")@@@list("jennifer_hsu" "2016/03/21 14:52:18" nil "p143000039-pc" "10i-core_combo_b2.20") | list("[Package] TOP" "149.Pkg to Pkg Spacing" "0 MIL [PACKAGE_HEIGHT_MIN]" "118.11 MIL" "-118.11 MIL" "DRC ERROR CLASS/PACKAGE_TOP" "[Shape] Package Geometry/Place_Bound_Top ((1412.5 3832.5) (1437.5 3857.5))" "[Shape] Package Geometry/Place_Bound_Top ((1283.17 3597.5) (1567.03 3952.7))" list(1425.000000 3857.500000) nil)@@@list("kelly1_pan" "2016/03/17 14:57:40" nil "P143000035-PC" "10i-core_combo_b2.20")@@@list("jennifer_hsu" "2016/03/21 14:52:15" nil "p143000039-pc" "10i-core_combo_b2.20") | list("[Package] TOP" "150.Pkg to Pkg Spacing" "0 MIL [PACKAGE_HEIGHT_MIN]" "118.11 MIL" "-118.11 MIL" "DRC ERROR CLASS/PACKAGE_TOP" "[Shape] Package Geometry/Place_Bound_Top ((1412.5 3692.5) (1437.5 3717.5))" "[Shape] Package Geometry/Place_Bound_Top ((1283.17 3597.5) (1567.03 3952.7))" list(1425.000000 3692.500000) nil)@@@list("kelly1_pan" "2016/03/17 14:57:41" nil "P143000035-PC" "10i-core_combo_b2.20")@@@list("jennifer_hsu" "2016/03/21 14:52:16" nil "p143000039-pc" "10i-core_combo_b2.20") | list("[Electrical] ALL" "139.Diffpair Max Uncoupled Length" "200 MIL [DIFFP_UNCOUPLED_LENGTH]" "207.92 MIL" "-7.92 MIL" "DRC ERROR CLASS/ALL" "[PinPair] <uTiL>cId3288<uTiL>.H13:<uTiL>cId5672<uTiL>.40 ((2139.78 2920.21) (1808.6 4506.53))" "[PinPair] <uTiL>cId3288<uTiL>.G13:<uTiL>cId5672<uTiL>.38 ((2139.78 2945.81) (1828.29 4506.53))" list(1828.290000 4506.530000) nil)@@@list("kelly1_pan" "2016/03/17 14:53:18" nil "P143000035-PC" "10i-core_combo_b2.20")@@@list("jennifer_hsu" "2016/03/21 14:52:03" nil "p143000039-pc" "10i-core_combo_b2.20") | list("[Package] TOP" "168.Pkg to Pkg Spacing" "0 MIL [PACKAGE_HEIGHT_MIN]" "118.11 MIL" "-118.11 MIL" "DRC ERROR CLASS/PACKAGE_TOP" "[Shape] Package Geometry/Place_Bound_Top ((1952.5 3797.5) (1977.5 3822.5))" "[Shape] Package Geometry/Place_Bound_Top ((1860.57 3604.51) (2069.63 3904.37))" list(1965.000000 3822.500000) nil)@@@list("kelly1_pan" "2016/03/17 15:00:51" nil "P143000035-PC" "10i-core_combo_b2.20")@@@list("jennifer_hsu" "2016/03/21 14:53:41" nil "p143000039-pc" "10i-core_combo_b2.20") | list("[Package] TOP" "167.Pkg to Pkg Spacing" "0 MIL [PACKAGE_HEIGHT_MIN]" "118.11 MIL" "-118.11 MIL" "DRC ERROR CLASS/PACKAGE_TOP" "[Shape] Package Geometry/Place_Bound_Top ((1952.5 3687.5) (1977.5 3712.5))" "[Shape] Package Geometry/Place_Bound_Top ((1860.57 3604.51) (2069.63 3904.37))" list(1965.000000 3687.500000) nil)@@@list("kelly1_pan" "2016/03/17 15:00:50" nil "P143000035-PC" "10i-core_combo_b2.20")@@@list("jennifer_hsu" "2016/03/21 14:53:40" nil "p143000039-pc" "10i-core_combo_b2.20") | list("[Package] BOTTOM" "269.Pkg to Place Keepin Spacing" "0 MIL [NONE]" "44.66 MIL" "-44.66 MIL" "DRC ERROR CLASS/PACKAGE_BOTTOM" "[Shape] Package Keepin/All ((-2957.43 -894.53) (7886.82 5054.84))" "[Shape] Package Geometry/Place_Bound_Bottom ((2007.48 4919.39) (2047.48 4959.39))" list(1982.490000 4985.830000) nil)@@@list("kelly1_pan" "2016/03/17 14:53:49" nil "P143000035-PC" "10i-core_combo_b2.20")@@@list("jennifer_hsu" "2016/03/21 14:55:26" nil "p143000039-pc" "10i-core_combo_b2.20") | list("[Package] TOP" "153.Pkg to Place Keepin Spacing" "0 MIL [NONE]" "44.66 MIL" "-44.66 MIL" "DRC ERROR CLASS/PACKAGE_TOP" "[Shape] Package Keepin/All ((-2957.43 -894.53) (7886.82 5054.84))" "[Shape] Package Geometry/Place_Bound_Top ((2007.48 4919.39) (2047.48 4959.39))" list(1982.490000 4985.830000) nil)@@@list("kelly1_pan" "2016/03/17 15:00:47" nil "P143000035-PC" "10i-core_combo_b2.20")@@@list("jennifer_hsu" "2016/03/21 14:52:19" nil "p143000039-pc" "10i-core_combo_b2.20") | list("[Electrical] ALL" "135.Diffpair Max Uncoupled Length" "200 MIL [DIFFP_UNCOUPLED_LENGTH]" "202.89 MIL" "-2.89 MIL" "DRC ERROR CLASS/ALL" "[PinPair] <uTiL>cId3288<uTiL>.B19:<uTiL>cId5672<uTiL>.58 ((1993.13 3078.61) (1631.44 4506.53))" "[PinPair] <uTiL>cId3288<uTiL>.A19:<uTiL>cId5672<uTiL>.56 ((1993.13 3104.21) (1651.12 4506.53))" list(1993.130000 3104.210000) nil)@@@list("kelly1_pan" "2016/03/17 14:53:15" nil "P143000035-PC" "10i-core_combo_b2.20")@@@list("jennifer_hsu" "2016/03/21 14:51:24" nil "p143000039-pc" "10i-core_combo_b2.20") | list("[Electrical] ALL" "125.Diffpair Max Uncoupled Length" "200 MIL [DIFFP_UNCOUPLED_LENGTH]" "200.86 MIL" "-0.86 MIL" "DRC ERROR CLASS/ALL" "[PinPair] <uTiL>cId6551<uTiL>.37:<uTiL>cId3288<uTiL>.C19 ((-1998.29 4100.46) (1993.13 3053.01))" "[PinPair] <uTiL>cId6551<uTiL>.35:<uTiL>cId3288<uTiL>.D19 ((-1998.29 4120.15) (1993.13 3027.41))" list(1993.130000 3027.410000) nil)@@@list("kelly1_pan" "2016/03/17 14:52:49" nil "P143000035-PC" "10i-core_combo_b2.20")@@@list("jennifer_hsu" "2016/03/21 14:51:06" nil "p143000039-pc" "10i-core_combo_b2.20") | list("[Electrical] ALL" "131.Diffpair Max Uncoupled Length" "200 MIL [DIFFP_UNCOUPLED_LENGTH]" "205.39 MIL" "-5.39 MIL" "DRC ERROR CLASS/ALL" "[PinPair] <uTiL>cId3288<uTiL>.E20:<uTiL>cId7381<uTiL>.7 ((1995.78 2997.01) (4803.87 259.29))" "[PinPair] <uTiL>cId3288<uTiL>.F20:<uTiL>cId7381<uTiL>.6 ((1995.78 2971.41) (4803.87 239.61))" list(1995.780000 2971.410000) nil)@@@list("kelly1_pan" "2016/03/17 14:53:12" nil "P143000035-PC" "10i-core_combo_b2.20")@@@list("jennifer_hsu" "2016/03/21 14:51:18" nil "p143000039-pc" "10i-core_combo_b2.20") | list("[Electrical] ALL" "133.Diffpair Max Uncoupled Length" "200 MIL [DIFFP_UNCOUPLED_LENGTH]" "226.14 MIL" "-26.14 MIL" "DRC ERROR CLASS/ALL" "[PinPair] <uTiL>cId5672<uTiL>.62:<uTiL>cId3288<uTiL>.A17 ((1592.07 4506.53) (2046.33 3104.21))" "[PinPair] <uTiL>cId5672<uTiL>.64:<uTiL>cId3288<uTiL>.B17 ((1572.38 4506.53) (2046.33 3078.61))" list(2046.330000 3078.610000) nil)@@@list("kelly1_pan" "2016/03/17 14:53:13" nil "P143000035-PC" "10i-core_combo_b2.20")@@@list("jennifer_hsu" "2016/03/21 14:51:21" nil "p143000039-pc" "10i-core_combo_b2.20") | list("[Electrical] ALL" "134.Diffpair Max Uncoupled Length" "200 MIL [DIFFP_UNCOUPLED_LENGTH]" "215.99 MIL" "-15.99 MIL" "DRC ERROR CLASS/ALL" "[PinPair] <uTiL>cId3288<uTiL>.D17:<uTiL>cId5672<uTiL>.52 ((2046.33 3027.41) (1690.49 4506.53))" "[PinPair] <uTiL>cId3288<uTiL>.C17:<uTiL>cId5672<uTiL>.50 ((2046.33 3053.01) (1710.18 4506.53))" list(2046.330000 3053.010000) nil)@@@list("kelly1_pan" "2016/03/17 14:53:14" nil "P143000035-PC" "10i-core_combo_b2.20")@@@list("jennifer_hsu" "2016/03/21 14:51:22" nil "p143000039-pc" "10i-core_combo_b2.20") | list("[Electrical] ALL" "136.Diffpair Max Uncoupled Length" "200 MIL [DIFFP_UNCOUPLED_LENGTH]" "295.46 MIL" "-95.46 MIL" "DRC ERROR CLASS/ALL" "[PinPair] <uTiL>cId5672<uTiL>.68:<uTiL>cId3288<uTiL>.C16 ((1533.01 4506.53) (2068.51 3065.81))" "[PinPair] <uTiL>cId5672<uTiL>.70:<uTiL>cId3288<uTiL>.D16 ((1513.33 4506.53) (2068.51 3040.21))" list(2068.510000 3040.210000) nil)@@@list("kelly1_pan" "2016/03/17 14:53:16" nil "P143000035-PC" "10i-core_combo_b2.20")@@@list("jennifer_hsu" "2016/03/21 14:51:25" nil "p143000039-pc" "10i-core_combo_b2.20") | list("[Electrical] ALL" "105.Diffpair Max Uncoupled Length" "200 MIL [DIFFP_UNCOUPLED_LENGTH]" "254.87 MIL" "-54.87 MIL" "DRC ERROR CLASS/ALL" "[PinPair] <uTiL>cId3288<uTiL>.B15:<uTiL>cId4180<uTiL>.28 ((2090.69 3078.61) (3184.45 2609.69))" "[PinPair] <uTiL>cId3288<uTiL>.A15:<uTiL>cId4180<uTiL>.29 ((2090.69 3104.21) (3184.45 2590.01))" list(2090.690000 3104.210000) nil)@@@list("kelly1_pan" "2016/03/17 14:52:07" nil "P143000035-PC" "10i-core_combo_b2.20")@@@list("jennifer_hsu" "2016/03/21 14:50:44" nil "p143000039-pc" "10i-core_combo_b2.20") | list("[Electrical] ALL" "103.Diffpair Max Uncoupled Length" "200 MIL [DIFFP_UNCOUPLED_LENGTH]" "247.72 MIL" "-47.72 MIL" "DRC ERROR CLASS/ALL" "[PinPair] <uTiL>cId3288<uTiL>.A13:<uTiL>cId6550<uTiL>.37 ((2143.89 3104.21) (1219.42 4201.25))" "[PinPair] <uTiL>cId3288<uTiL>.B13:<uTiL>cId6550<uTiL>.35 ((2143.89 3078.61) (1219.42 4181.56))" list(2143.890000 3078.610000) nil)@@@list("kelly1_pan" "2016/03/17 14:52:05" nil "P143000035-PC" "10i-core_combo_b2.20")@@@list("jennifer_hsu" "2016/03/21 14:50:42" nil "p143000039-pc" "10i-core_combo_b2.20") | list("[Package] BOTTOM" "222.Pkg to Place Keepin Spacing" "0 MIL [NONE]" "44.68 MIL" "-44.68 MIL" "DRC ERROR CLASS/PACKAGE_BOTTOM" "[Shape] Package Keepin/All ((-2957.43 -894.53) (7886.82 5054.84))" "[Shape] Package Geometry/Place_Bound_Bottom ((2290.95 4939.07) (2330.95 4979.07))" list(2355.960000 5005.520000) nil)@@@list("kelly1_pan" "2016/03/17 14:53:48" nil "P143000035-PC" "10i-core_combo_b2.20")@@@list("jennifer_hsu" "2016/03/21 14:54:34" nil "p143000039-pc" "10i-core_combo_b2.20") | list("[Package] TOP" "194.Pkg to Place Keepin Spacing" "0 MIL [NONE]" "44.68 MIL" "-44.68 MIL" "DRC ERROR CLASS/PACKAGE_TOP" "[Shape] Package Keepin/All ((-2957.43 -894.53) (7886.82 5054.84))" "[Shape] Package Geometry/Place_Bound_Top ((2290.95 4939.07) (2330.95 4979.07))" list(2355.960000 5005.520000) nil)@@@list("kelly1_pan" "2016/03/17 15:00:54" nil "P143000035-PC" "10i-core_combo_b2.20")@@@list("jennifer_hsu" "2016/03/21 14:54:06" nil "p143000039-pc" "10i-core_combo_b2.20") | list("[Electrical] ALL" "112.Diffpair Max Uncoupled Length" "200 MIL [DIFFP_UNCOUPLED_LENGTH]" "224.25 MIL" "-24.25 MIL" "DRC ERROR CLASS/ALL" "[PinPair] <uTiL>cId7251<uTiL>.8:<uTiL>cId3288<uTiL>.AH1 ((3619.23 532.9) (2411.71 2522.27))" "[PinPair] <uTiL>cId7251<uTiL>.9:<uTiL>cId3288<uTiL>.AH2 ((3638.92 643.14) (2386.11 2522.27))" list(2386.110000 2522.270000) nil)@@@list("kelly1_pan" "2016/03/17 14:52:17" nil "P143000035-PC" "10i-core_combo_b2.20")@@@list("jennifer_hsu" "2016/03/21 14:50:52" nil "p143000039-pc" "10i-core_combo_b2.20") | list("[Electrical] ALL" "110.Diffpair Max Uncoupled Length" "200 MIL [DIFFP_UNCOUPLED_LENGTH]" "224.43 MIL" "-24.43 MIL" "DRC ERROR CLASS/ALL" "[PinPair] <uTiL>cId4160<uTiL>.3:<uTiL>cId3288<uTiL>.AJ2 ((2953.67 4590.03) (2398.91 2496.17))" "[PinPair] <uTiL>cId4160<uTiL>.2:<uTiL>cId3288<uTiL>.AJ1 ((3032.41 4590.03) (2424.51 2496.17))" list(2424.510000 2496.170000) nil)@@@list("kelly1_pan" "2016/03/17 14:52:15" nil "P143000035-PC" "10i-core_combo_b2.20")@@@list("jennifer_hsu" "2016/03/21 14:50:49" nil "p143000039-pc" "10i-core_combo_b2.20") | list("[Package] BOTTOM" "241.Pkg to Place Keepin Spacing" "0 MIL [NONE]" "0 MIL" "0.00 MIL" "DRC ERROR CLASS/PACKAGE_BOTTOM" "[Shape] Package Keepin/All ((-2957.43 -894.53) (7886.82 5054.84))" "[Shape] Package Geometry/Place_Bound_Bottom ((2646.35 4552.52) (3339.73 5143.38))" list(2670.010000 5054.840000) nil)@@@list("kelly1_pan" "2016/03/17 14:57:16" nil "P143000035-PC" "10i-core_combo_b2.20")@@@list("jennifer_hsu" "2016/03/21 14:54:52" nil "p143000039-pc" "10i-core_combo_b2.20") | list("[Package] BOTTOM" "257.Pkg to Place Keepin Spacing" "0 MIL [NONE]" "44.67 MIL" "-44.67 MIL" "DRC ERROR CLASS/PACKAGE_BOTTOM" "[Shape] Package Keepin/All ((-2957.43 -894.53) (7886.82 5054.84))" "[Shape] Package Geometry/Place_Bound_Bottom ((2705.32 4625.13) (2745.32 4665.13))" list(2680.330000 4691.590000) nil)@@@list("kelly1_pan" "2016/03/17 14:53:33" nil "P143000035-PC" "10i-core_combo_b2.20")@@@list("jennifer_hsu" "2016/03/21 14:55:11" nil "p143000039-pc" "10i-core_combo_b2.20") | list("[Package] TOP" "142.Pkg to Place Keepin Spacing" "0 MIL [NONE]" "44.67 MIL" "-44.67 MIL" "DRC ERROR CLASS/PACKAGE_TOP" "[Shape] Package Keepin/All ((-2957.43 -894.53) (7886.82 5054.84))" "[Shape] Package Geometry/Place_Bound_Top ((2705.32 4625.13) (2745.32 4665.13))" list(2680.330000 4691.590000) nil)@@@list("kelly1_pan" "2016/03/17 14:59:16" nil "P143000035-PC" "10i-core_combo_b2.20")@@@list("jennifer_hsu" "2016/03/21 14:52:06" nil "p143000039-pc" "10i-core_combo_b2.20") | list("[Electrical] ALL" "109.Diffpair Max Uncoupled Length" "200 MIL [DIFFP_UNCOUPLED_LENGTH]" "203.78 MIL" "-3.78 MIL" "DRC ERROR CLASS/ALL" "[PinPair] <uTiL>cId4160<uTiL>.2:<uTiL>cId3288<uTiL>.AJ1 ((3032.41 4590.03) (2424.51 2496.17))" "[PinPair] <uTiL>cId4160<uTiL>.3:<uTiL>cId3288<uTiL>.AJ2 ((2953.67 4590.03) (2398.91 2496.17))" list(2953.670000 4590.030000) nil)@@@list("kelly1_pan" "2016/03/17 14:52:14" nil "P143000035-PC" "10i-core_combo_b2.20")@@@list("jennifer_hsu" "2016/03/21 14:50:48" nil "p143000039-pc" "10i-core_combo_b2.20") | list("[Package] BOTTOM" "247.Pkg to Pkg Spacing" "0 MIL [PACKAGE_HEIGHT_MIN]" "167.32 MIL" "-167.32 MIL" "DRC ERROR CLASS/PACKAGE_BOTTOM" "[Shape] Package Geometry/Place_Bound_Bottom ((-26.77 5.29) (3048.69 1006.72))" "[Shape] Package Geometry/Place_Bound_Bottom ((61.88 528.95) (2959.92 1532.35))" list(2959.920000 1006.720000) nil)@@@list("kelly1_pan" "2016/03/17 14:57:04" nil "P143000035-PC" "10i-core_combo_b2.20")@@@list("jennifer_hsu" "2016/03/21 14:54:58" nil "p143000039-pc" "10i-core_combo_b2.20") | list("[Package] BOTTOM" "281.Pkg to Pkg Spacing" "0 MIL [PACKAGE_HEIGHT_MIN]" "234.25 MIL" "-234.25 MIL" "DRC ERROR CLASS/PACKAGE_BOTTOM" "[Shape] Package Geometry/Place_Bound_Bottom ((-26.77 5.29) (3048.69 1006.72))" "[Shape] Package Geometry/Place_Bound_Bottom ((3035.55 -61.78) (3335.57 781.14))" list(3035.550000 604.650000) nil)@@@list("kelly1_pan" "2016/03/17 14:53:44" nil "P143000035-PC" "10i-core_combo_b2.20")@@@list("jennifer_hsu" "2016/03/21 14:55:38" nil "p143000039-pc" "10i-core_combo_b2.20") | list("[Package] BOTTOM" "235.Pkg to Pkg Spacing" "0 MIL [PACKAGE_HEIGHT_MIN]" "39.37 MIL" "-39.37 MIL" "DRC ERROR CLASS/PACKAGE_BOTTOM" "[Shape] Package Geometry/Place_Bound_Bottom ((3100.69 4321.98) (3187.31 4444.02))" "[Shape] Package Geometry/Place_Bound_Bottom ((3108.37 4319.81) (3179.63 4446.19))" list(3108.370000 4321.980000) nil)@@@list("kelly1_pan" "2016/03/17 14:53:29" nil "P143000035-PC" "10i-core_combo_b2.20")@@@list("jennifer_hsu" "2016/03/21 14:54:47" nil "p143000039-pc" "10i-core_combo_b2.20") | list("[Package] BOTTOM" "203.Pkg to Pkg Spacing" "62.99 MIL [PACKAGE_HEIGHT_MIN]" "80.71 MIL" "-17.72 MIL" "DRC ERROR CLASS/PACKAGE_BOTTOM" "[Shape] Package Geometry/Place_Bound_Bottom ((2980.85 3163.62) (3414.31 3471.89))" "[Shape] Package Geometry/Place_Bound_Bottom ((3152.94 1952.02) (3412.99 3247.68))" list(3184.250000 3163.620000) nil)@@@list("kelly1_pan" "2016/03/17 14:57:13" nil "P143000035-PC" "10i-core_combo_b2.20")@@@list("jennifer_hsu" "2016/03/21 14:54:15" nil "p143000039-pc" "10i-core_combo_b2.20") | list("[Electrical] ALL" "108.Diffpair Max Uncoupled Length" "200 MIL [DIFFP_UNCOUPLED_LENGTH]" "229.2 MIL" "-29.20 MIL" "DRC ERROR CLASS/ALL" "[PinPair] <uTiL>cId4180<uTiL>.32:<uTiL>cId3288<uTiL>.J10 ((3184.45 2530.95) (2211.78 2894.61))" "[PinPair] <uTiL>cId4180<uTiL>.31:<uTiL>cId3288<uTiL>.H10 ((3184.45 2550.64) (2211.78 2920.21))" list(3184.450000 2550.640000) nil)@@@list("kelly1_pan" "2016/03/17 14:52:13" nil "P143000035-PC" "10i-core_combo_b2.20")@@@list("jennifer_hsu" "2016/03/21 14:50:47" nil "p143000039-pc" "10i-core_combo_b2.20") | list("[Electrical] ALL" "107.Diffpair Max Uncoupled Length" "200 MIL [DIFFP_UNCOUPLED_LENGTH]" "213.56 MIL" "-13.56 MIL" "DRC ERROR CLASS/ALL" "[PinPair] <uTiL>cId4180<uTiL>.35:<uTiL>cId3288<uTiL>.AJ3 ((3184.45 2471.9) (2373.31 2496.17))" "[PinPair] <uTiL>cId4180<uTiL>.34:<uTiL>cId3288<uTiL>.AH3 ((3184.45 2491.58) (2360.51 2522.27))" list(3184.450000 2491.580000) nil)@@@list("kelly1_pan" "2016/03/17 14:52:12" nil "P143000035-PC" "10i-core_combo_b2.20")@@@list("jennifer_hsu" "2016/03/21 14:50:46" nil "p143000039-pc" "10i-core_combo_b2.20") | list("[Package] BOTTOM" "270.Pkg to Place Keepin Spacing" "0 MIL [NONE]" "44.69 MIL" "-44.69 MIL" "DRC ERROR CLASS/PACKAGE_BOTTOM" "[Shape] Package Keepin/All ((-2957.43 -894.53) (7886.82 5054.84))" "[Shape] Package Geometry/Place_Bound_Bottom ((3240.75 4625.13) (3280.75 4665.13))" list(3214.300000 4600.110000) nil)@@@list("kelly1_pan" "2016/03/17 14:53:22" nil "P143000035-PC" "10i-core_combo_b2.20")@@@list("jennifer_hsu" "2016/03/21 14:55:27" nil "p143000039-pc" "10i-core_combo_b2.20") | list("[Package] TOP" "158.Pkg to Place Keepin Spacing" "0 MIL [NONE]" "44.69 MIL" "-44.69 MIL" "DRC ERROR CLASS/PACKAGE_TOP" "[Shape] Package Keepin/All ((-2957.43 -894.53) (7886.82 5054.84))" "[Shape] Package Geometry/Place_Bound_Top ((3240.75 4625.13) (3280.75 4665.13))" list(3214.300000 4600.110000) nil)@@@list("kelly1_pan" "2016/03/17 14:57:33" nil "P143000035-PC" "10i-core_combo_b2.20")@@@list("jennifer_hsu" "2016/03/21 14:52:28" nil "p143000039-pc" "10i-core_combo_b2.20") | list("[Package] BOTTOM" "265.Pkg to Pkg Spacing" "0 MIL [PACKAGE_HEIGHT_MIN]" "85.04 MIL" "-85.04 MIL" "DRC ERROR CLASS/PACKAGE_BOTTOM" "[Shape] Package Geometry/Place_Bound_Bottom ((2980.85 3347.67) (3414.31 3820.51))" "[Shape] Package Geometry/Place_Bound_Bottom ((3079.27 3392.56) (3315.89 3775.62))" list(3359.190000 3735.960000) nil)@@@list("kelly1_pan" "2016/03/17 14:57:12" nil "P143000035-PC" "10i-core_combo_b2.20")@@@list("jennifer_hsu" "2016/03/21 14:55:21" nil "p143000039-pc" "10i-core_combo_b2.20") | list("[Package] BOTTOM" "221.Pkg to Place Keepin Spacing" "0 MIL [NONE]" "0 MIL" "0.00 MIL" "DRC ERROR CLASS/PACKAGE_BOTTOM" "[Shape] Package Keepin/All ((-2957.43 -894.53) (7886.82 5054.84))" "[Shape] Package Geometry/Place_Bound_Bottom ((3367.74 4461.65) (4241.1 5321.72))" list(3367.740000 5054.840000) nil)@@@list("kelly1_pan" "2016/03/17 14:53:21" nil "P143000035-PC" "10i-core_combo_b2.20")@@@list("jennifer_hsu" "2016/03/21 14:54:33" nil "p143000039-pc" "10i-core_combo_b2.20") | list("[Package] BOTTOM" "224.Pkg to Place Keepin Spacing" "0 MIL [NONE]" "44.66 MIL" "-44.66 MIL" "DRC ERROR CLASS/PACKAGE_BOTTOM" "[Shape] Package Keepin/All ((-2957.43 -894.53) (7886.82 5054.84))" "[Shape] Package Geometry/Place_Bound_Bottom ((3449.77 4696.0) (3489.77 4736.0))" list(3424.780000 4762.440000) nil)@@@list("kelly1_pan" "2016/03/17 14:53:32" nil "P143000035-PC" "10i-core_combo_b2.20")@@@list("jennifer_hsu" "2016/03/21 14:54:36" nil "p143000039-pc" "10i-core_combo_b2.20") | list("[Package] TOP" "184.Pkg to Place Keepin Spacing" "0 MIL [NONE]" "44.66 MIL" "-44.66 MIL" "DRC ERROR CLASS/PACKAGE_TOP" "[Shape] Package Keepin/All ((-2957.43 -894.53) (7886.82 5054.84))" "[Shape] Package Geometry/Place_Bound_Top ((3449.77 4696.0) (3489.77 4736.0))" list(3424.780000 4762.440000) nil)@@@list("kelly1_pan" "2016/03/17 14:59:16" nil "P143000035-PC" "10i-core_combo_b2.20")@@@list("jennifer_hsu" "2016/03/21 14:53:56" nil "p143000039-pc" "10i-core_combo_b2.20") | list("[Package] BOTTOM" "243.Pkg to Pkg Spacing" "0 MIL [PACKAGE_HEIGHT_MIN]" "27.56 MIL" "-27.56 MIL" "DRC ERROR CLASS/PACKAGE_BOTTOM" "[Shape] Package Geometry/Place_Bound_Bottom ((3579.47 2676.91) (3650.73 2803.29))" "[Shape] Package Geometry/Place_Bound_Bottom ((3571.79 2679.08) (3658.41 2801.12))" list(3579.470000 2679.080000) nil)@@@list("kelly1_pan" "2016/03/17 14:57:11" nil "P143000035-PC" "10i-core_combo_b2.20")@@@list("jennifer_hsu" "2016/03/21 14:54:55" nil "p143000039-pc" "10i-core_combo_b2.20") | list("[Package] BOTTOM" "1.Pkg to Pkg Spacing" "0 MIL [PACKAGE_HEIGHT_MIN]" "27.56 MIL" "-27.56 MIL" "DRC ERROR CLASS/PACKAGE_BOTTOM" "[Shape] Package Geometry/Place_Bound_Bottom ((3579.47 2486.81) (3650.73 2613.19))" "[Shape] Package Geometry/Place_Bound_Bottom ((3571.79 2488.98) (3658.41 2611.02))" list(3579.470000 2488.980000) nil)@@@list("kelly1_pan" "2016/03/17 14:57:17" nil "P143000035-PC" "10i-core_combo_b2.20")@@@list("jennifer_hsu" "2016/03/21 14:59:44" nil "P143000039-PC" "10i-core_combo_b2.20") | list("[Package] BOTTOM" "261.Pkg to Pkg Spacing" "0 MIL [PACKAGE_HEIGHT_MIN]" "27.56 MIL" "-27.56 MIL" "DRC ERROR CLASS/PACKAGE_BOTTOM" "[Shape] Package Geometry/Place_Bound_Bottom ((3584.37 2291.81) (3655.63 2418.19))" "[Shape] Package Geometry/Place_Bound_Bottom ((3576.69 2293.98) (3663.31 2416.02))" list(3584.370000 2293.980000) nil)@@@list("kelly1_pan" "2016/03/17 14:53:25" nil "P143000035-PC" "10i-core_combo_b2.20")@@@list("jennifer_hsu" "2016/03/21 14:55:16" nil "p143000039-pc" "10i-core_combo_b2.20") | list("[Electrical] ALL" "113.Diffpair Max Uncoupled Length" "200 MIL [DIFFP_UNCOUPLED_LENGTH]" "208.19 MIL" "-8.19 MIL" "DRC ERROR CLASS/ALL" "[PinPair] <uTiL>cId7251<uTiL>.9:<uTiL>cId3288<uTiL>.AH2 ((3638.92 643.14) (2386.11 2522.27))" "[PinPair] <uTiL>cId7251<uTiL>.8:<uTiL>cId3288<uTiL>.AH1 ((3619.23 532.9) (2411.71 2522.27))" list(3619.230000 532.900000) nil)@@@list("kelly1_pan" "2016/03/17 14:52:18" nil "P143000035-PC" "10i-core_combo_b2.20")@@@list("jennifer_hsu" "2016/03/21 14:50:52" nil "p143000039-pc" "10i-core_combo_b2.20") | list("[Electrical] ALL" "137.Diffpair Max Uncoupled Length" "200 MIL [DIFFP_UNCOUPLED_LENGTH]" "205.06 MIL" "-5.06 MIL" "DRC ERROR CLASS/ALL" "[PinPair] <uTiL>cId4167<uTiL>.8:<uTiL>cId3288<uTiL>.AF7 ((3813.56 1038.8) (2291.48 2580.01))" "[PinPair] <uTiL>cId4167<uTiL>.7:<uTiL>cId3288<uTiL>.AF6 ((3813.56 1058.49) (2317.08 2580.01))" list(3813.560000 1058.490000) nil)@@@list("kelly1_pan" "2016/03/17 14:53:17" nil "P143000035-PC" "10i-core_combo_b2.20")@@@list("jennifer_hsu" "2016/03/21 14:52:01" nil "p143000039-pc" "10i-core_combo_b2.20") | list("[Electrical] ALL" "130.Diffpair Max Uncoupled Length" "200 MIL [DIFFP_UNCOUPLED_LENGTH]" "217.96 MIL" "-17.96 MIL" "DRC ERROR CLASS/ALL" "[PinPair] <uTiL>cId4178<uTiL>.4:<uTiL>cId3288<uTiL>.D20 ((3892.45 1320.32) (1970.95 3040.21))" "[PinPair] <uTiL>cId4178<uTiL>.3:<uTiL>cId3288<uTiL>.C20 ((3872.77 1320.32) (1970.95 3065.81))" list(3872.770000 1320.320000) nil)@@@list("kelly1_pan" "2016/03/17 14:53:11" nil "P143000035-PC" "10i-core_combo_b2.20")@@@list("jennifer_hsu" "2016/03/21 14:51:16" nil "p143000039-pc" "10i-core_combo_b2.20") | list("[Package] TOP" "157.Pkg to Pkg Spacing" "0 MIL [PACKAGE_HEIGHT_MIN]" "2 MIL" "-2.00 MIL" "DRC ERROR CLASS/PACKAGE_TOP" "[Shape] Package Geometry/Place_Bound_Top ((3852.77 241.59) (4037.43 328.61))" "[Shape] Package Geometry/Place_Bound_Top ((3897.5 272.5) (3922.5 297.5))" list(3897.500000 272.500000) nil)@@@list("kelly1_pan" "2016/03/17 15:00:35" nil "P143000035-PC" "10i-core_combo_b2.20")@@@list("jennifer_hsu" "2016/03/21 14:52:23" nil "p143000039-pc" "10i-core_combo_b2.20") | list("[Package] BOTTOM" "273.Pkg to Place Keepin Spacing" "0 MIL [NONE]" "0 MIL" "0.00 MIL" "DRC ERROR CLASS/PACKAGE_BOTTOM" "[Shape] Package Keepin/All ((-2957.43 -894.53) (7886.82 5054.84))" "[Shape] Package Geometry/Place_Bound_Bottom ((3853.29 -146.03) (4140.29 140.97))" list(3902.920000 -111.070000) nil)@@@list("kelly1_pan" "2016/03/17 14:57:09" nil "P143000035-PC" "10i-core_combo_b2.20")@@@list("jennifer_hsu" "2016/03/21 14:55:29" nil "p143000039-pc" "10i-core_combo_b2.20") | list("[Package] TOP" "161.Pkg to Place Keepin Spacing" "0 MIL [NONE]" "0 MIL" "0.00 MIL" "DRC ERROR CLASS/PACKAGE_TOP" "[Shape] Package Keepin/All ((-2957.43 -894.53) (7886.82 5054.84))" "[Shape] Package Geometry/Place_Bound_Top ((3853.29 -146.03) (4140.29 140.97))" list(3902.920000 -111.070000) nil)@@@list("kelly1_pan" "2016/03/17 14:57:48" nil "P143000035-PC" "10i-core_combo_b2.20")@@@list("jennifer_hsu" "2016/03/21 14:52:32" nil "p143000039-pc" "10i-core_combo_b2.20") | list("[Package] BOTTOM" "278.Pkg to Pkg Spacing" "0 MIL [PACKAGE_HEIGHT_MIN]" "82.68 MIL" "-82.68 MIL" "DRC ERROR CLASS/PACKAGE_BOTTOM" "[Shape] Package Geometry/Place_Bound_Bottom ((3683.59 1286.82) (4711.55 1621.7))" "[Shape] Package Geometry/Place_Bound_Bottom ((3776.06 768.85) (4071.63 1289.07))" list(3963.370000 1286.820000) nil)@@@list("kelly1_pan" "2016/03/17 14:53:27" nil "P143000035-PC" "10i-core_combo_b2.20")@@@list("jennifer_hsu" "2016/03/21 14:55:34" nil "p143000039-pc" "10i-core_combo_b2.20") | list("[Package] TOP" "192.Pkg to Pkg Spacing" "0 MIL [PACKAGE_HEIGHT_MIN]" "2 MIL" "-2.00 MIL" "DRC ERROR CLASS/PACKAGE_TOP" "[Shape] Package Geometry/Place_Bound_Top ((3852.77 241.59) (4037.43 328.61))" "[Shape] Package Geometry/Place_Bound_Top ((3967.5 272.5) (3992.5 297.5))" list(3967.500000 272.500000) nil)@@@list("kelly1_pan" "2016/03/17 15:00:49" nil "P143000035-PC" "10i-core_combo_b2.20")@@@list("jennifer_hsu" "2016/03/21 14:54:04" nil "p143000039-pc" "10i-core_combo_b2.20") | list("[Electrical] ALL" "115.Diffpair Max Uncoupled Length" "200 MIL [DIFFP_UNCOUPLED_LENGTH]" "268.06 MIL" "-68.06 MIL" "DRC ERROR CLASS/ALL" "[PinPair] <uTiL>cId4174<uTiL>.49:<uTiL>cId3288<uTiL>.D13 ((3992.72 2337.24) (2143.89 3027.41))" "[PinPair] <uTiL>cId4174<uTiL>.48:<uTiL>cId3288<uTiL>.C13 ((3992.72 2356.92) (2143.89 3053.01))" list(3992.720000 2356.920000) nil)@@@list("kelly1_pan" "2016/03/17 14:52:37" nil "P143000035-PC" "10i-core_combo_b2.20")@@@list("jennifer_hsu" "2016/03/21 14:50:55" nil "p143000039-pc" "10i-core_combo_b2.20") | list("[Package] BOTTOM" "209.Pkg to Pkg Spacing" "0 MIL [PACKAGE_HEIGHT_MIN]" "2 MIL" "-2.00 MIL" "DRC ERROR CLASS/PACKAGE_BOTTOM" "[Shape] Package Geometry/Place_Bound_Bottom ((3765.12 1863.54) (4154.88 2056.46))" "[Shape] Package Geometry/Place_Bound_Bottom ((4032.5 1972.5) (4057.5 1997.5))" list(4032.500000 1972.500000) nil)@@@list("kelly1_pan" "2016/03/17 14:53:28" nil "P143000035-PC" "10i-core_combo_b2.20")@@@list("jennifer_hsu" "2016/03/21 14:54:21" nil "p143000039-pc" "10i-core_combo_b2.20") | list("[Package] BOTTOM" "263.Pkg to Pkg Spacing" "0 MIL [PACKAGE_HEIGHT_MIN]" "2 MIL" "-2.00 MIL" "DRC ERROR CLASS/PACKAGE_BOTTOM" "[Shape] Package Geometry/Place_Bound_Bottom ((3765.12 1863.54) (4154.88 2056.46))" "[Shape] Package Geometry/Place_Bound_Bottom ((4032.5 1917.5) (4057.5 1942.5))" list(4032.500000 1917.500000) nil)@@@list("kelly1_pan" "2016/03/17 14:57:24" nil "P143000035-PC" "10i-core_combo_b2.20")@@@list("jennifer_hsu" "2016/03/21 14:55:18" nil "p143000039-pc" "10i-core_combo_b2.20") | list("[Package] BOTTOM" "233.Pkg to Pkg Spacing" "0 MIL [PACKAGE_HEIGHT_MIN]" "27.56 MIL" "-27.56 MIL" "DRC ERROR CLASS/PACKAGE_BOTTOM" "[Shape] Package Geometry/Place_Bound_Bottom ((4054.51 658.93) (4125.77 785.31))" "[Shape] Package Geometry/Place_Bound_Bottom ((4046.83 661.1) (4133.45 783.14))" list(4054.510000 661.100000) nil)@@@list("kelly1_pan" "2016/03/17 14:57:01" nil "P143000035-PC" "10i-core_combo_b2.20")@@@list("jennifer_hsu" "2016/03/21 14:54:45" nil "p143000039-pc" "10i-core_combo_b2.20") | list("[Electrical] ALL" "114.Diffpair Max Uncoupled Length" "200 MIL [DIFFP_UNCOUPLED_LENGTH]" "266.35 MIL" "-66.35 MIL" "DRC ERROR CLASS/ALL" "[PinPair] <uTiL>cId3291<uTiL>.7:<uTiL>cId4179<uTiL>.46 ((4176.73 4264.37) (-1623.28 3063.42))" "[PinPair] <uTiL>cId3291<uTiL>.6:<uTiL>cId4179<uTiL>.47 ((4176.73 4244.69) (-1642.97 3063.42))" list(4176.730000 4244.690000) nil)@@@list("kelly1_pan" "2016/03/17 14:52:36" nil "P143000035-PC" "10i-core_combo_b2.20")@@@list("jennifer_hsu" "2016/03/21 14:50:54" nil "p143000039-pc" "10i-core_combo_b2.20") | list("[Electrical] ALL" "138.Diffpair Max Uncoupled Length" "200 MIL [DIFFP_UNCOUPLED_LENGTH]" "215.76 MIL" "-15.76 MIL" "DRC ERROR CLASS/ALL" "[PinPair] <uTiL>cId3291<uTiL>.2:<uTiL>cId4179<uTiL>.27 ((4176.73 4165.94) (-1249.27 3063.42))" "[PinPair] <uTiL>cId3291<uTiL>.1:<uTiL>cId4179<uTiL>.28 ((4176.73 4146.26) (-1268.95 3063.42))" list(4176.730000 4146.260000) nil)@@@list("kelly1_pan" "2016/03/17 14:53:17" nil "P143000035-PC" "10i-core_combo_b2.20")@@@list("jennifer_hsu" "2016/03/21 14:52:02" nil "p143000039-pc" "10i-core_combo_b2.20") | list("[Package] BOTTOM" "223.Pkg to Place Keepin Spacing" "0 MIL [NONE]" "44.67 MIL" "-44.67 MIL" "DRC ERROR CLASS/PACKAGE_BOTTOM" "[Shape] Package Keepin/All ((-2957.43 -894.53) (7886.82 5054.84))" "[Shape] Package Geometry/Place_Bound_Bottom ((4119.06 4696.0) (4159.06 4736.0))" list(4184.070000 4762.440000) nil)@@@list("kelly1_pan" "2016/03/17 14:57:07" nil "P143000035-PC" "10i-core_combo_b2.20")@@@list("jennifer_hsu" "2016/03/21 14:54:35" nil "p143000039-pc" "10i-core_combo_b2.20") | list("[Package] TOP" "176.Pkg to Place Keepin Spacing" "0 MIL [NONE]" "44.67 MIL" "-44.67 MIL" "DRC ERROR CLASS/PACKAGE_TOP" "[Shape] Package Keepin/All ((-2957.43 -894.53) (7886.82 5054.84))" "[Shape] Package Geometry/Place_Bound_Top ((4119.06 4696.0) (4159.06 4736.0))" list(4184.070000 4762.440000) nil)@@@list("kelly1_pan" "2016/03/17 14:57:26" nil "P143000035-PC" "10i-core_combo_b2.20")@@@list("jennifer_hsu" "2016/03/21 14:53:48" nil "p143000039-pc" "10i-core_combo_b2.20") | list("[Package] BOTTOM" "218.Pkg to Pkg Spacing" "0 MIL [PACKAGE_HEIGHT_MIN]" "27.56 MIL" "-27.56 MIL" "DRC ERROR CLASS/PACKAGE_BOTTOM" "[Shape] Package Geometry/Place_Bound_Bottom ((4219.47 1111.91) (4290.73 1238.29))" "[Shape] Package Geometry/Place_Bound_Bottom ((4211.79 1114.08) (4298.41 1236.12))" list(4219.470000 1114.080000) nil)@@@list("kelly1_pan" "2016/03/17 14:57:23" nil "P143000035-PC" "10i-core_combo_b2.20")@@@list("jennifer_hsu" "2016/03/21 14:54:30" nil "p143000039-pc" "10i-core_combo_b2.20") | list("[Package] BOTTOM" "262.Pkg to Pkg Spacing" "0 MIL [PACKAGE_HEIGHT_MIN]" "27.56 MIL" "-27.56 MIL" "DRC ERROR CLASS/PACKAGE_BOTTOM" "[Shape] Package Geometry/Place_Bound_Bottom ((4430.87 3782.31) (4502.13 3908.69))" "[Shape] Package Geometry/Place_Bound_Bottom ((4423.19 3784.48) (4509.81 3906.52))" list(4430.870000 3784.480000) nil)@@@list("kelly1_pan" "2016/03/17 14:53:27" nil "P143000035-PC" "10i-core_combo_b2.20")@@@list("jennifer_hsu" "2016/03/21 14:55:17" nil "p143000039-pc" "10i-core_combo_b2.20") | list("[Package] TOP" "202.Pkg to Place Keepin Spacing" "0 MIL [NONE]" "0 MIL" "0.00 MIL" "DRC ERROR CLASS/PACKAGE_TOP" "[Shape] Package Keepin/All ((-2957.43 -894.53) (7886.82 5054.84))" "[Shape] Package Geometry/Place_Bound_Top ((4320.54 3630.98) (4649.47 4029.02))" list(4575.010000 3910.910000) nil)@@@list("kelly1_pan" "2016/03/17 14:57:46" nil "P143000035-PC" "10i-core_combo_b2.20")@@@list("jennifer_hsu" "2016/03/21 14:54:15" nil "p143000039-pc" "10i-core_combo_b2.20") | list("[Package] BOTTOM" "242.Pkg to Place Keepin Spacing" "0 MIL [NONE]" "0 MIL" "0.00 MIL" "DRC ERROR CLASS/PACKAGE_BOTTOM" "[Shape] Package Keepin/All ((-2957.43 -894.53) (7886.82 5054.84))" "[Shape] Package Geometry/Place_Bound_Bottom ((4658.4 4838.25) (4945.4 5125.25))" list(4678.410000 5054.840000) nil)@@@list("kelly1_pan" "2016/03/17 14:53:24" nil "P143000035-PC" "10i-core_combo_b2.20")@@@list("jennifer_hsu" "2016/03/21 14:54:54" nil "p143000039-pc" "10i-core_combo_b2.20") | list("[Package] TOP" "147.Pkg to Place Keepin Spacing" "0 MIL [NONE]" "0 MIL" "0.00 MIL" "DRC ERROR CLASS/PACKAGE_TOP" "[Shape] Package Keepin/All ((-2957.43 -894.53) (7886.82 5054.84))" "[Shape] Package Geometry/Place_Bound_Top ((4658.4 4838.25) (4945.4 5125.25))" list(4678.410000 5054.840000) nil)@@@list("kelly1_pan" "2016/03/17 14:57:36" nil "P143000035-PC" "10i-core_combo_b2.20")@@@list("jennifer_hsu" "2016/03/21 14:52:13" nil "p143000039-pc" "10i-core_combo_b2.20") | list("[Package] TOP" "174.Pkg to Pkg Spacing" "0 MIL [PACKAGE_HEIGHT_MIN]" "2 MIL" "-2.00 MIL" "DRC ERROR CLASS/PACKAGE_TOP" "[Shape] Package Geometry/Place_Bound_Top ((4610.12 863.54) (4999.88 1056.46))" "[Shape] Package Geometry/Place_Bound_Top ((4877.5 952.5) (4902.5 977.5))" list(4877.500000 952.500000) nil)@@@list("kelly1_pan" "2016/03/17 14:59:14" nil "P143000035-PC" "10i-core_combo_b2.20")@@@list("jennifer_hsu" "2016/03/21 14:53:46" nil "p143000039-pc" "10i-core_combo_b2.20") | list("[Package] BOTTOM" "208.Pkg to Place Keepin Spacing" "0 MIL [NONE]" "0 MIL" "0.00 MIL" "DRC ERROR CLASS/PACKAGE_BOTTOM" "[Shape] Package Keepin/All ((-2957.43 -894.53) (7886.82 5054.84))" "[Shape] Package Geometry/Place_Bound_Bottom ((5015.07 2985.49) (5315.09 3828.41))" list(5058.700000 3789.790000) nil)@@@list("kelly1_pan" "2016/03/17 14:57:15" nil "P143000035-PC" "10i-core_combo_b2.20")@@@list("jennifer_hsu" "2016/03/21 14:54:20" nil "p143000039-pc" "10i-core_combo_b2.20") | list("[Package] TOP" "200.Pkg to Pkg Spacing" "0 MIL [PACKAGE_HEIGHT_MIN]" "27.56 MIL" "-27.56 MIL" "DRC ERROR CLASS/PACKAGE_TOP" "[Shape] Package Geometry/Place_Bound_Top ((5110.37 4737.81) (5181.63 4864.19))" "[Shape] Package Geometry/Place_Bound_Top ((5102.69 4739.98) (5189.31 4862.02))" list(5110.370000 4739.980000) nil)@@@list("kelly1_pan" "2016/03/17 14:57:37" nil "P143000035-PC" "10i-core_combo_b2.20")@@@list("jennifer_hsu" "2016/03/21 14:54:12" nil "p143000039-pc" "10i-core_combo_b2.20") | list("[Package] BOTTOM" "207.Pkg to Place Keepin Spacing" "0 MIL [NONE]" "0 MIL" "0.00 MIL" "DRC ERROR CLASS/PACKAGE_BOTTOM" "[Shape] Package Keepin/All ((-2957.43 -894.53) (7886.82 5054.84))" "[Shape] Package Geometry/Place_Bound_Bottom ((5156.44 3889.23) (5372.98 4105.77))" list(5184.850000 4070.610000) nil)@@@list("kelly1_pan" "2016/03/17 14:55:32" nil "P143000035-PC" "10i-core_combo_b2.20")@@@list("jennifer_hsu" "2016/03/21 14:54:19" nil "p143000039-pc" "10i-core_combo_b2.20") | list("[Package] TOP" "172.Pkg to Place Keepin Spacing" "0 MIL [NONE]" "0 MIL" "0.00 MIL" "DRC ERROR CLASS/PACKAGE_TOP" "[Shape] Package Keepin/All ((-2957.43 -894.53) (7886.82 5054.84))" "[Shape] Package Geometry/Place_Bound_Top ((5156.44 3889.23) (5372.98 4105.77))" list(5184.850000 4070.610000) nil)@@@list("kelly1_pan" "2016/03/17 15:00:58" nil "P143000035-PC" "10i-core_combo_b2.20")@@@list("jennifer_hsu" "2016/03/21 14:53:44" nil "p143000039-pc" "10i-core_combo_b2.20") | list("[Package] BOTTOM" "231.Pkg to Place Keepin Spacing" "0 MIL [NONE]" "0 MIL" "0.00 MIL" "DRC ERROR CLASS/PACKAGE_BOTTOM" "[Shape] Package Keepin/All ((-2957.43 -894.53) (7886.82 5054.84))" "[Shape] Package Geometry/Place_Bound_Bottom ((5211.55 1596.1) (5498.55 1883.1))" list(5254.760000 1842.240000) nil)@@@list("kelly1_pan" "2016/03/17 14:55:33" nil "P143000035-PC" "10i-core_combo_b2.20")@@@list("jennifer_hsu" "2016/03/21 14:54:43" nil "p143000039-pc" "10i-core_combo_b2.20") | list("[Package] TOP" "198.Pkg to Place Keepin Spacing" "0 MIL [NONE]" "0 MIL" "0.00 MIL" "DRC ERROR CLASS/PACKAGE_TOP" "[Shape] Package Keepin/All ((-2957.43 -894.53) (7886.82 5054.84))" "[Shape] Package Geometry/Place_Bound_Top ((5211.55 1596.1) (5498.55 1883.1))" list(5254.760000 1842.240000) nil)@@@list("kelly1_pan" "2016/03/17 15:00:59" nil "P143000035-PC" "10i-core_combo_b2.20")@@@list("jennifer_hsu" "2016/03/21 14:54:10" nil "p143000039-pc" "10i-core_combo_b2.20") | list("[Package] BOTTOM" "229.Pkg to Place Keepin Spacing" "0 MIL [NONE]" "0 MIL" "0.00 MIL" "DRC ERROR CLASS/PACKAGE_BOTTOM" "[Shape] Package Keepin/All ((-2957.43 -894.53) (7886.82 5054.84))" "[Shape] Package Geometry/Place_Bound_Bottom ((5156.44 2708.12) (5372.98 2924.66))" list(5324.790000 2906.460000) nil)@@@list("kelly1_pan" "2016/03/17 14:55:30" nil "P143000035-PC" "10i-core_combo_b2.20")@@@list("jennifer_hsu" "2016/03/21 14:54:41" nil "p143000039-pc" "10i-core_combo_b2.20") | list("[Package] TOP" "171.Pkg to Place Keepin Spacing" "0 MIL [NONE]" "0 MIL" "0.00 MIL" "DRC ERROR CLASS/PACKAGE_TOP" "[Shape] Package Keepin/All ((-2957.43 -894.53) (7886.82 5054.84))" "[Shape] Package Geometry/Place_Bound_Top ((5156.44 2708.12) (5372.98 2924.66))" list(5324.790000 2906.460000) nil)@@@list("kelly1_pan" "2016/03/17 15:00:57" nil "P143000035-PC" "10i-core_combo_b2.20")@@@list("jennifer_hsu" "2016/03/21 14:53:43" nil "p143000039-pc" "10i-core_combo_b2.20") | list("[Package] BOTTOM" "264.Pkg to Place Keepin Spacing" "0 MIL [NONE]" "0 MIL" "0.00 MIL" "DRC ERROR CLASS/PACKAGE_BOTTOM" "[Shape] Package Keepin/All ((-2957.43 -894.53) (7886.82 5054.84))" "[Shape] Package Geometry/Place_Bound_Bottom ((5336.95 2917.44) (5758.61 3896.44))" list(5341.950000 3881.550000) nil)@@@list("kelly1_pan" "2016/03/17 14:57:18" nil "P143000035-PC" "10i-core_combo_b2.20")@@@list("jennifer_hsu" "2016/03/21 14:55:20" nil "p143000039-pc" "10i-core_combo_b2.20") | list("[Package] TOP" "201.Pkg to Pkg Spacing" "0 MIL [PACKAGE_HEIGHT_MIN]" "2 MIL" "-2.00 MIL" "DRC ERROR CLASS/PACKAGE_TOP" "[Shape] Package Geometry/Place_Bound_Top ((5322.67 -48.51) (5507.33 38.51))" "[Shape] Package Geometry/Place_Bound_Top ((5367.5 -17.5) (5392.5 7.5))" list(5367.500000 -17.500000) nil)@@@list("kelly1_pan" "2016/03/17 14:59:13" nil "P143000035-PC" "10i-core_combo_b2.20")@@@list("jennifer_hsu" "2016/03/21 14:54:13" nil "p143000039-pc" "10i-core_combo_b2.20") | list("[Package] BOTTOM" "240.Pkg to Place Keepin Spacing" "0 MIL [NONE]" "1485.05 MIL" "-1485.05 MIL" "DRC ERROR CLASS/PACKAGE_BOTTOM" "[Shape] Package Keepin/All ((-2957.43 -894.53) (7886.82 5054.84))" "[Shape] Package Geometry/Place_Bound_Bottom ((6760.78 5539.82) (6950.9 5729.94))" list(5386.040000 5054.840000) nil)@@@list("kelly1_pan" "2016/03/17 14:57:14" nil "P143000035-PC" "10i-core_combo_b2.20")@@@list("jennifer_hsu" "2016/03/21 14:54:51" nil "p143000039-pc" "10i-core_combo_b2.20") | list("[Package] TOP" "144.Pkg to Place Keepin Spacing" "0 MIL [NONE]" "485.14 MIL" "-485.14 MIL" "DRC ERROR CLASS/PACKAGE_TOP" "[Shape] Package Keepin/All ((-2957.43 -894.53) (7886.82 5054.84))" "[Shape] Package Geometry/Place_Bound_Top ((5304.68 5539.82) (5494.8 5729.94))" list(5386.040000 5054.840000) nil)@@@list("kelly1_pan" "2016/03/17 14:57:47" nil "P143000035-PC" "10i-core_combo_b2.20")@@@list("jennifer_hsu" "2016/03/21 14:52:09" nil "p143000039-pc" "10i-core_combo_b2.20") | list("[Package] BOTTOM" "251.Pkg to Place Keepin Spacing" "0 MIL [NONE]" "1005.84 MIL" "-1005.84 MIL" "DRC ERROR CLASS/PACKAGE_BOTTOM" "[Shape] Package Keepin/All ((-2957.43 -894.53) (7886.82 5054.84))" "[Shape] Package Geometry/Place_Bound_Bottom ((5304.68 -1307.03) (5494.8 -1116.91))" list(5399.750000 -111.070000) nil)@@@list("kelly1_pan" "2016/03/17 14:55:29" nil "P143000035-PC" "10i-core_combo_b2.20")@@@list("jennifer_hsu" "2016/03/21 14:55:03" nil "p143000039-pc" "10i-core_combo_b2.20") | list("[Package] TOP" "166.Pkg to Pkg Spacing" "0 MIL [PACKAGE_HEIGHT_MIN]" "2 MIL" "-2.00 MIL" "DRC ERROR CLASS/PACKAGE_TOP" "[Shape] Package Geometry/Place_Bound_Top ((5322.67 -48.51) (5507.33 38.51))" "[Shape] Package Geometry/Place_Bound_Top ((5437.5 -17.5) (5462.5 7.5))" list(5437.500000 -17.500000) nil)@@@list("kelly1_pan" "2016/03/17 15:01:02" nil "P143000035-PC" "10i-core_combo_b2.20")@@@list("jennifer_hsu" "2016/03/21 14:53:39" nil "p143000039-pc" "10i-core_combo_b2.20") | list("[Package] TOP" "148.Pkg to Place Keepin Spacing" "0 MIL [NONE]" "0 MIL" "0.00 MIL" "DRC ERROR CLASS/PACKAGE_TOP" "[Shape] Package Keepin/All ((-2957.43 -894.53) (7886.82 5054.84))" "[Shape] Package Geometry/Place_Bound_Top ((6391.4 3022.99) (6950.98 3318.56))" list(6420.920000 3066.200000) nil)@@@list("kelly1_pan" "2016/03/17 14:57:39" nil "P143000035-PC" "10i-core_combo_b2.20")@@@list("jennifer_hsu" "2016/03/21 14:52:14" nil "p143000039-pc" "10i-core_combo_b2.20") | list("[Package] BOTTOM" "217.Pkg to Place Keepin Spacing" "0 MIL [NONE]" "0 MIL" "0.00 MIL" "DRC ERROR CLASS/PACKAGE_BOTTOM" "[Shape] Package Keepin/All ((-2957.43 -894.53) (7886.82 5054.84))" "[Shape] Package Geometry/Place_Bound_Bottom ((6607.21 1615.81) (6894.21 1902.81))" list(6633.600000 1842.240000) nil)@@@list("kelly1_pan" "2016/03/17 14:57:20" nil "P143000035-PC" "10i-core_combo_b2.20")@@@list("jennifer_hsu" "2016/03/21 14:54:29" nil "p143000039-pc" "10i-core_combo_b2.20") | list("[Package] TOP" "199.Pkg to Place Keepin Spacing" "0 MIL [NONE]" "0 MIL" "0.00 MIL" "DRC ERROR CLASS/PACKAGE_TOP" "[Shape] Package Keepin/All ((-2957.43 -894.53) (7886.82 5054.84))" "[Shape] Package Geometry/Place_Bound_Top ((6607.21 1615.81) (6894.21 1902.81))" list(6633.600000 1842.240000) nil)@@@list("kelly1_pan" "2016/03/17 14:57:31" nil "P143000035-PC" "10i-core_combo_b2.20")@@@list("jennifer_hsu" "2016/03/21 14:54:11" nil "p143000039-pc" "10i-core_combo_b2.20") | list("[Package] BOTTOM" "245.Pkg to Place Keepin Spacing" "0 MIL [NONE]" "0 MIL" "0.00 MIL" "DRC ERROR CLASS/PACKAGE_BOTTOM" "[Shape] Package Keepin/All ((-2957.43 -894.53) (7886.82 5054.84))" "[Shape] Package Geometry/Place_Bound_Bottom ((7023.55 2450.26) (7240.09 2666.8))" list(7029.630000 2522.770000) nil)@@@list("kelly1_pan" "2016/03/17 14:53:45" nil "P143000035-PC" "10i-core_combo_b2.20")@@@list("jennifer_hsu" "2016/03/21 14:54:56" nil "p143000039-pc" "10i-core_combo_b2.20") | list("[Package] TOP" "175.Pkg to Place Keepin Spacing" "0 MIL [NONE]" "0 MIL" "0.00 MIL" "DRC ERROR CLASS/PACKAGE_TOP" "[Shape] Package Keepin/All ((-2957.43 -894.53) (7886.82 5054.84))" "[Shape] Package Geometry/Place_Bound_Top ((7023.55 2450.26) (7240.09 2666.8))" list(7029.630000 2522.770000) nil)@@@list("kelly1_pan" "2016/03/17 15:00:49" nil "P143000035-PC" "10i-core_combo_b2.20")@@@list("jennifer_hsu" "2016/03/21 14:53:47" nil "p143000039-pc" "10i-core_combo_b2.20") | list("[Package] TOP" "188.Pkg to Place Keepin Spacing" "0 MIL [NONE]" "1666.05 MIL" "-1666.05 MIL" "DRC ERROR CLASS/PACKAGE_TOP" "[Shape] Package Keepin/All ((-2957.43 -894.53) (7886.82 5054.84))" "[Shape] Package Geometry/Place_Bound_Top ((6960.78 5539.82) (7150.9 5729.94))" list(7055.850000 3873.770000) nil)@@@list("kelly1_pan" "2016/03/17 14:57:44" nil "P143000035-PC" "10i-core_combo_b2.20")@@@list("jennifer_hsu" "2016/03/21 14:54:00" nil "p143000039-pc" "10i-core_combo_b2.20") | list("[Package] BOTTOM" "279.Pkg to Place Keepin Spacing" "0 MIL [NONE]" "0 MIL" "0.00 MIL" "DRC ERROR CLASS/PACKAGE_BOTTOM" "[Shape] Package Keepin/All ((-2957.43 -894.53) (7886.82 5054.84))" "[Shape] Package Geometry/Place_Bound_Bottom ((7108.73 -874.77) (7550.21 -579.2))" list(7130.370000 -874.770000) nil)@@@list("kelly1_pan" "2016/03/17 14:53:37" nil "P143000035-PC" "10i-core_combo_b2.20")@@@list("jennifer_hsu" "2016/03/21 14:55:36" nil "p143000039-pc" "10i-core_combo_b2.20") | list("[Package] BOTTOM" "215.Pkg to Place Keepin Spacing" "0 MIL [NONE]" "1850.15 MIL" "-1850.15 MIL" "DRC ERROR CLASS/PACKAGE_BOTTOM" "[Shape] Package Keepin/All ((-2957.43 -894.53) (7886.82 5054.84))" "[Shape] Package Geometry/Place_Bound_Bottom ((8025.84 5554.88) (8185.84 5714.88))" list(7318.660000 3872.550000) nil)@@@list("kelly1_pan" "2016/03/17 14:57:13" nil "P143000035-PC" "10i-core_combo_b2.20")@@@list("jennifer_hsu" "2016/03/21 14:54:27" nil "p143000039-pc" "10i-core_combo_b2.20") | list("[Package] TOP" "196.Pkg to Place Keepin Spacing" "0 MIL [NONE]" "1850.15 MIL" "-1850.15 MIL" "DRC ERROR CLASS/PACKAGE_TOP" "[Shape] Package Keepin/All ((-2957.43 -894.53) (7886.82 5054.84))" "[Shape] Package Geometry/Place_Bound_Top ((8025.84 5554.88) (8185.84 5714.88))" list(7318.660000 3872.550000) nil)@@@list("kelly1_pan" "2016/03/17 15:00:55" nil "P143000035-PC" "10i-core_combo_b2.20")@@@list("jennifer_hsu" "2016/03/21 14:54:08" nil "p143000039-pc" "10i-core_combo_b2.20") | list("[Package] BOTTOM" "210.Pkg to Place Keepin Spacing" "0 MIL [NONE]" "0 MIL" "0.00 MIL" "DRC ERROR CLASS/PACKAGE_BOTTOM" "[Shape] Package Keepin/All ((-2957.43 -894.53) (7886.82 5054.84))" "[Shape] Package Geometry/Place_Bound_Bottom ((6814.66 3453.53) (7435.16 3873.75))" list(7326.670000 3862.660000) nil)@@@list("kelly1_pan" "2016/03/17 14:53:20" nil "P143000035-PC" "10i-core_combo_b2.20")@@@list("jennifer_hsu" "2016/03/21 14:54:22" nil "p143000039-pc" "10i-core_combo_b2.20") | list("[Package] BOTTOM" "244.Pkg to Place Keepin Spacing" "0 MIL [NONE]" "0 MIL" "0.00 MIL" "DRC ERROR CLASS/PACKAGE_BOTTOM" "[Shape] Package Keepin/All ((-2957.43 -894.53) (7886.82 5054.84))" "[Shape] Package Geometry/Place_Bound_Bottom ((6713.71 2727.43) (7390.04 3330.61))" list(7326.980000 2727.430000) nil)@@@list("kelly1_pan" "2016/03/17 14:53:30" nil "P143000035-PC" "10i-core_combo_b2.20")@@@list("jennifer_hsu" "2016/03/21 14:54:55" nil "p143000039-pc" "10i-core_combo_b2.20") | list("[Package] BOTTOM" "239.Pkg to Place Keepin Spacing" "0 MIL [NONE]" "222.38 MIL" "-222.38 MIL" "DRC ERROR CLASS/PACKAGE_BOTTOM" "[Shape] Package Keepin/All ((-2957.43 -894.53) (7886.82 5054.84))" "[Shape] Package Geometry/Place_Bound_Bottom ((7460.78 -1307.03) (7650.9 -1116.91))" list(7555.850000 -894.530000) nil)@@@list("kelly1_pan" "2016/03/17 14:53:23" nil "P143000035-PC" "10i-core_combo_b2.20")@@@list("jennifer_hsu" "2016/03/21 14:54:50" nil "p143000039-pc" "10i-core_combo_b2.20") | list("[Package] TOP" "160.Pkg to Place Keepin Spacing" "0 MIL [NONE]" "222.38 MIL" "-222.38 MIL" "DRC ERROR CLASS/PACKAGE_TOP" "[Shape] Package Keepin/All ((-2957.43 -894.53) (7886.82 5054.84))" "[Shape] Package Geometry/Place_Bound_Top ((7660.78 -1307.03) (7850.9 -1116.91))" list(7755.830000 -894.530000) nil)@@@list("kelly1_pan" "2016/03/17 14:57:44" nil "P143000035-PC" "10i-core_combo_b2.20")@@@list("jennifer_hsu" "2016/03/21 14:52:30" nil "p143000039-pc" "10i-core_combo_b2.20") | list("[Package] BOTTOM" "214.Pkg to Place Keepin Spacing" "0 MIL [NONE]" "368.93 MIL" "-368.93 MIL" "DRC ERROR CLASS/PACKAGE_BOTTOM" "[Shape] Package Keepin/All ((-2957.43 -894.53) (7886.82 5054.84))" "[Shape] Package Geometry/Place_Bound_Bottom ((8025.84 -1291.97) (8185.84 -1131.97))" list(7788.400000 -894.530000) nil)@@@list("kelly1_pan" "2016/03/17 14:53:42" nil "P143000035-PC" "10i-core_combo_b2.20")@@@list("jennifer_hsu" "2016/03/21 14:54:26" nil "p143000039-pc" "10i-core_combo_b2.20") | list("[Package] TOP" "143.Pkg to Place Keepin Spacing" "0 MIL [NONE]" "368.93 MIL" "-368.93 MIL" "DRC ERROR CLASS/PACKAGE_TOP" "[Shape] Package Keepin/All ((-2957.43 -894.53) (7886.82 5054.84))" "[Shape] Package Geometry/Place_Bound_Top ((8025.84 -1291.97) (8185.84 -1131.97))" list(7788.400000 -894.530000) nil)@@@list("kelly1_pan" "2016/03/17 14:57:33" nil "P143000035-PC" "10i-core_combo_b2.20")@@@list("jennifer_hsu" "2016/03/21 14:52:07" nil "p143000039-pc" "10i-core_combo_b2.20") | list("[Package] BOTTOM" "232.Pkg to Pkg Spacing" "0 MIL [PACKAGE_HEIGHT_MIN]" "0 MIL" "0.00 MIL" "DRC ERROR CLASS/PACKAGE_BOTTOM" "[Shape] Package Geometry/Place_Bound_Bottom ((7815.71 -750.5) (7874.71 -691.5))" "[Shape] Package Geometry/Place_Bound_Bottom ((7552.11 -864.53) (7839.11 -577.53))" list(7836.320000 -692.870000) nil)@@@list("kelly1_pan" "2016/03/17 14:57:10" nil "P143000035-PC" "10i-core_combo_b2.20")@@@list("jennifer_hsu" "2016/03/21 14:54:44" nil "p143000039-pc" "10i-core_combo_b2.20") | list("[Package] TOP" "190.Pkg to Pkg Spacing" "0 MIL [PACKAGE_HEIGHT_MIN]" "0 MIL" "0.00 MIL" "DRC ERROR CLASS/PACKAGE_TOP" "[Shape] Package Geometry/Place_Bound_Top ((7815.71 -750.5) (7874.71 -691.5))" "[Shape] Package Geometry/Place_Bound_Top ((7552.11 -864.53) (7839.11 -577.53))" list(7836.320000 -692.870000) nil)@@@list("kelly1_pan" "2016/03/17 14:59:10" nil "P143000035-PC" "10i-core_combo_b2.20")@@@list("jennifer_hsu" "2016/03/21 14:54:02" nil "p143000039-pc" "10i-core_combo_b2.20") | FIGURE | SIZE | 8.0 | 10.0 | 12.0 | 18.0 | 21.0 | 27.0 | 28.0 | 30.0 | 31.0 | 35.0 | 38.0 | 44.0 | 91.0 | 98.0 | 110.0 | 122.0 | 126.0 | 146.0 | 150.0 | 177.0 | 181.0 | 40.0 | 41.0 | 43.0 | 49.0 | 58.0 | 59.0 | 63.0 | 160.0 | 49.0x18.0 | 51.0x20.0 | 67.0x28.0 | 75.0x31.0 | 98.0x24.0 | 98.0x26.0 | 99.0x18.0 | 101.0x22.0 | 101.0x30.0 | 112.0x39.0 | 58.0x49.0 | 108.0x59.0 | 335.0x217.0 | DRILL CHART: TOP to BOTTOM (1 to 10) | ALL UNITS ARE IN MILS | TOLERANCE | +3.0/-3.0 | +2.0/-2.0 | +4.0/-4.0 | PLATED | NON-PLATED | ROTATION | - | 0.000 | 90.000 | 150.000 | QTY | 56 | 5885 | 96 | 466 | 19 | 5 | 8 | 9 | 4 | 2 | 10 | 1 | 3 | 20 | 7 | 6676 | TOTAL HOLES:
